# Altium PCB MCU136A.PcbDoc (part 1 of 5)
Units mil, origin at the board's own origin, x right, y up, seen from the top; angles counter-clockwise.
Board outline 3937.01 x 4724.41 mil, 4 copper layers (Top Layer, Signal Layer 1, Signal Layer 2, Bottom Layer), stack 60 mil thick; 390 components, 224 nets, 1130 pads, 1344 vias.
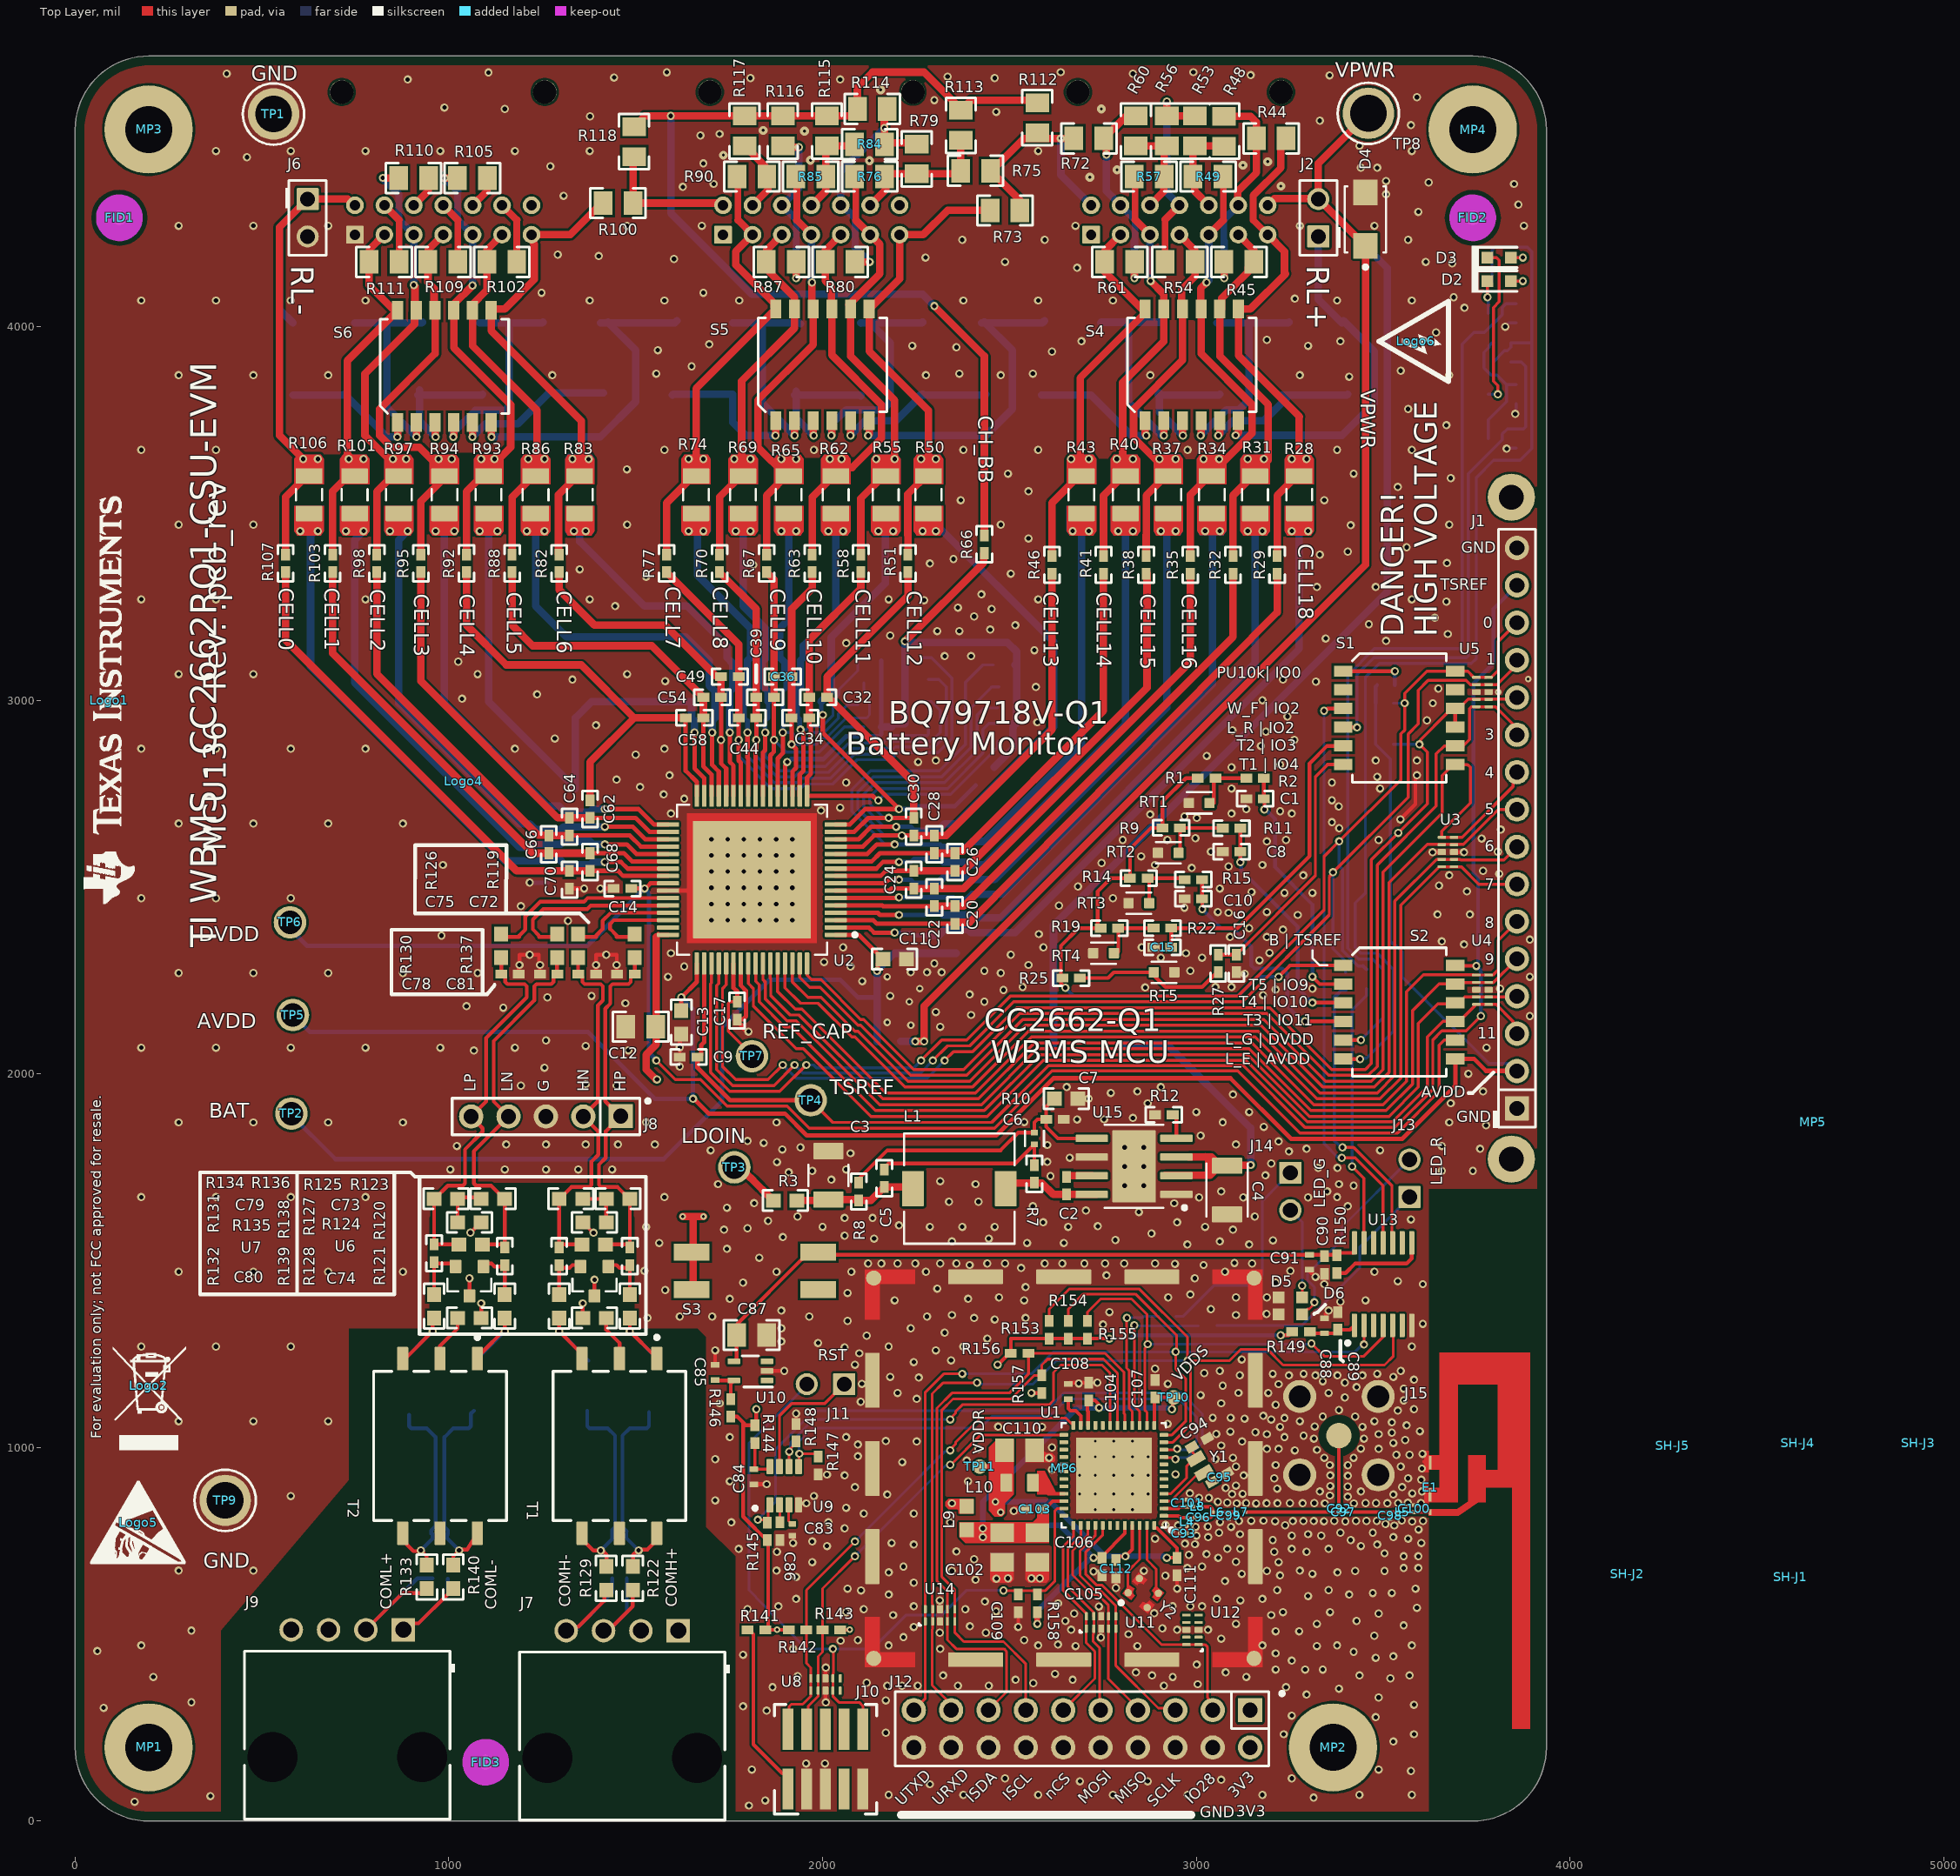
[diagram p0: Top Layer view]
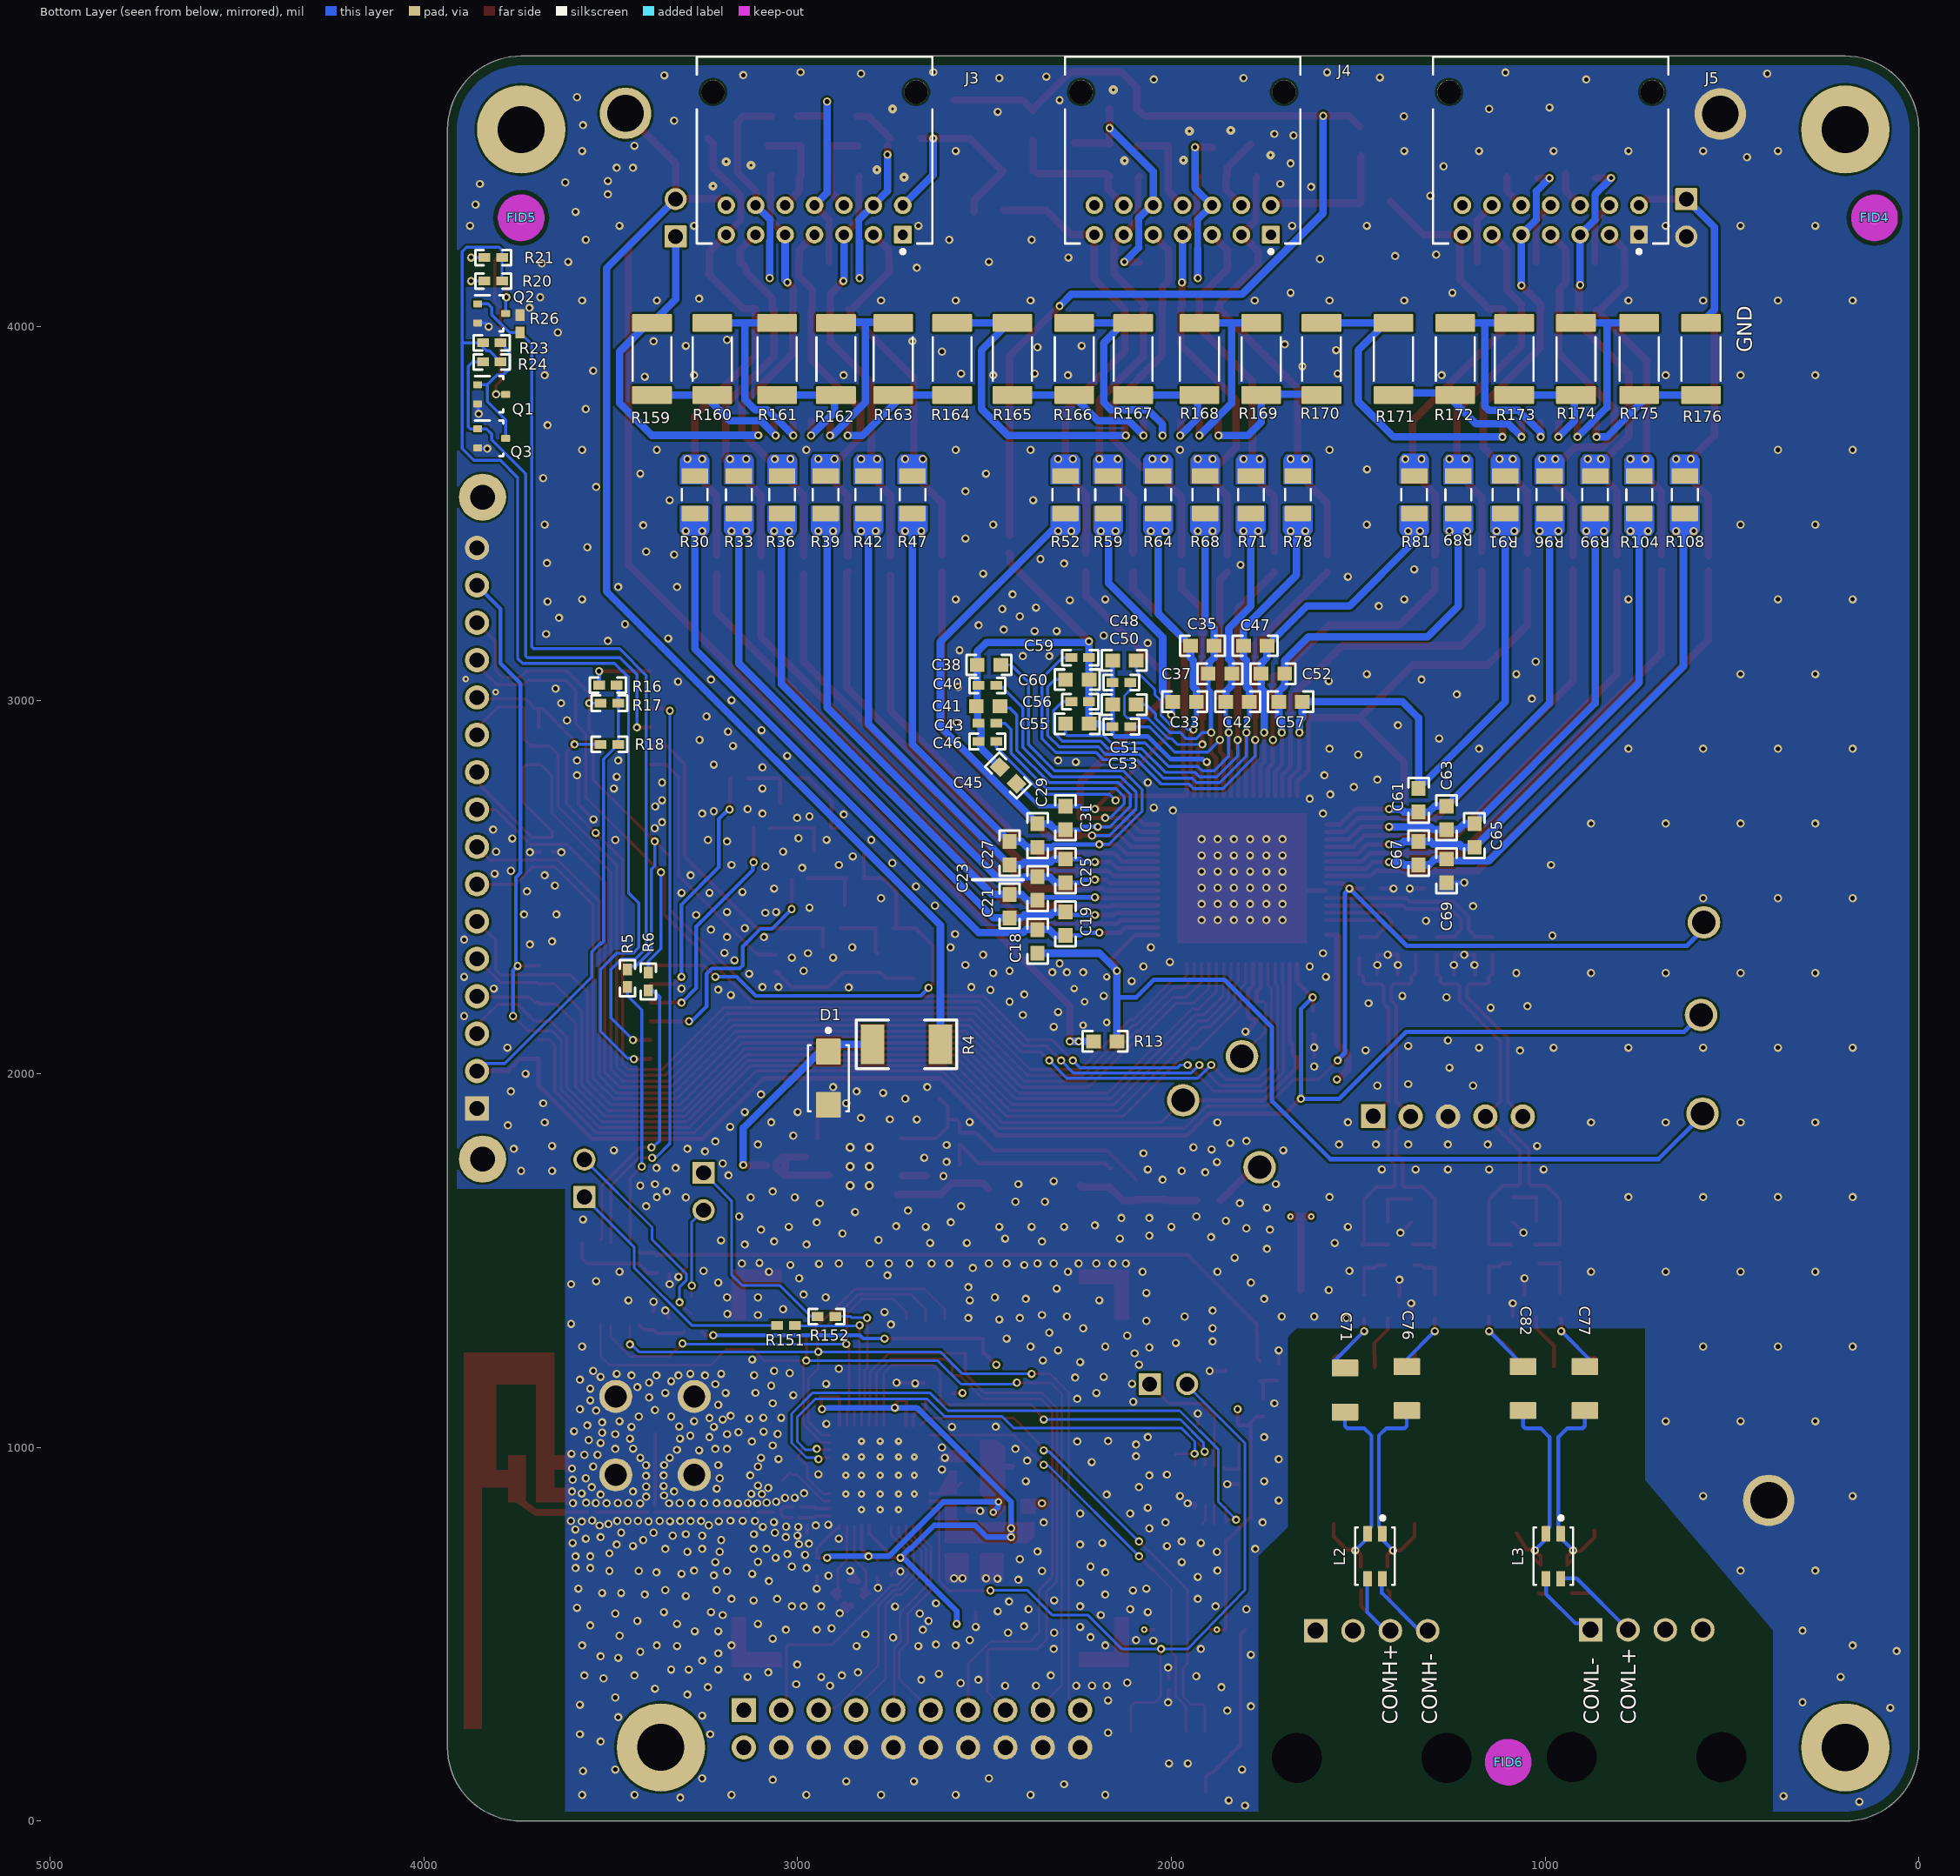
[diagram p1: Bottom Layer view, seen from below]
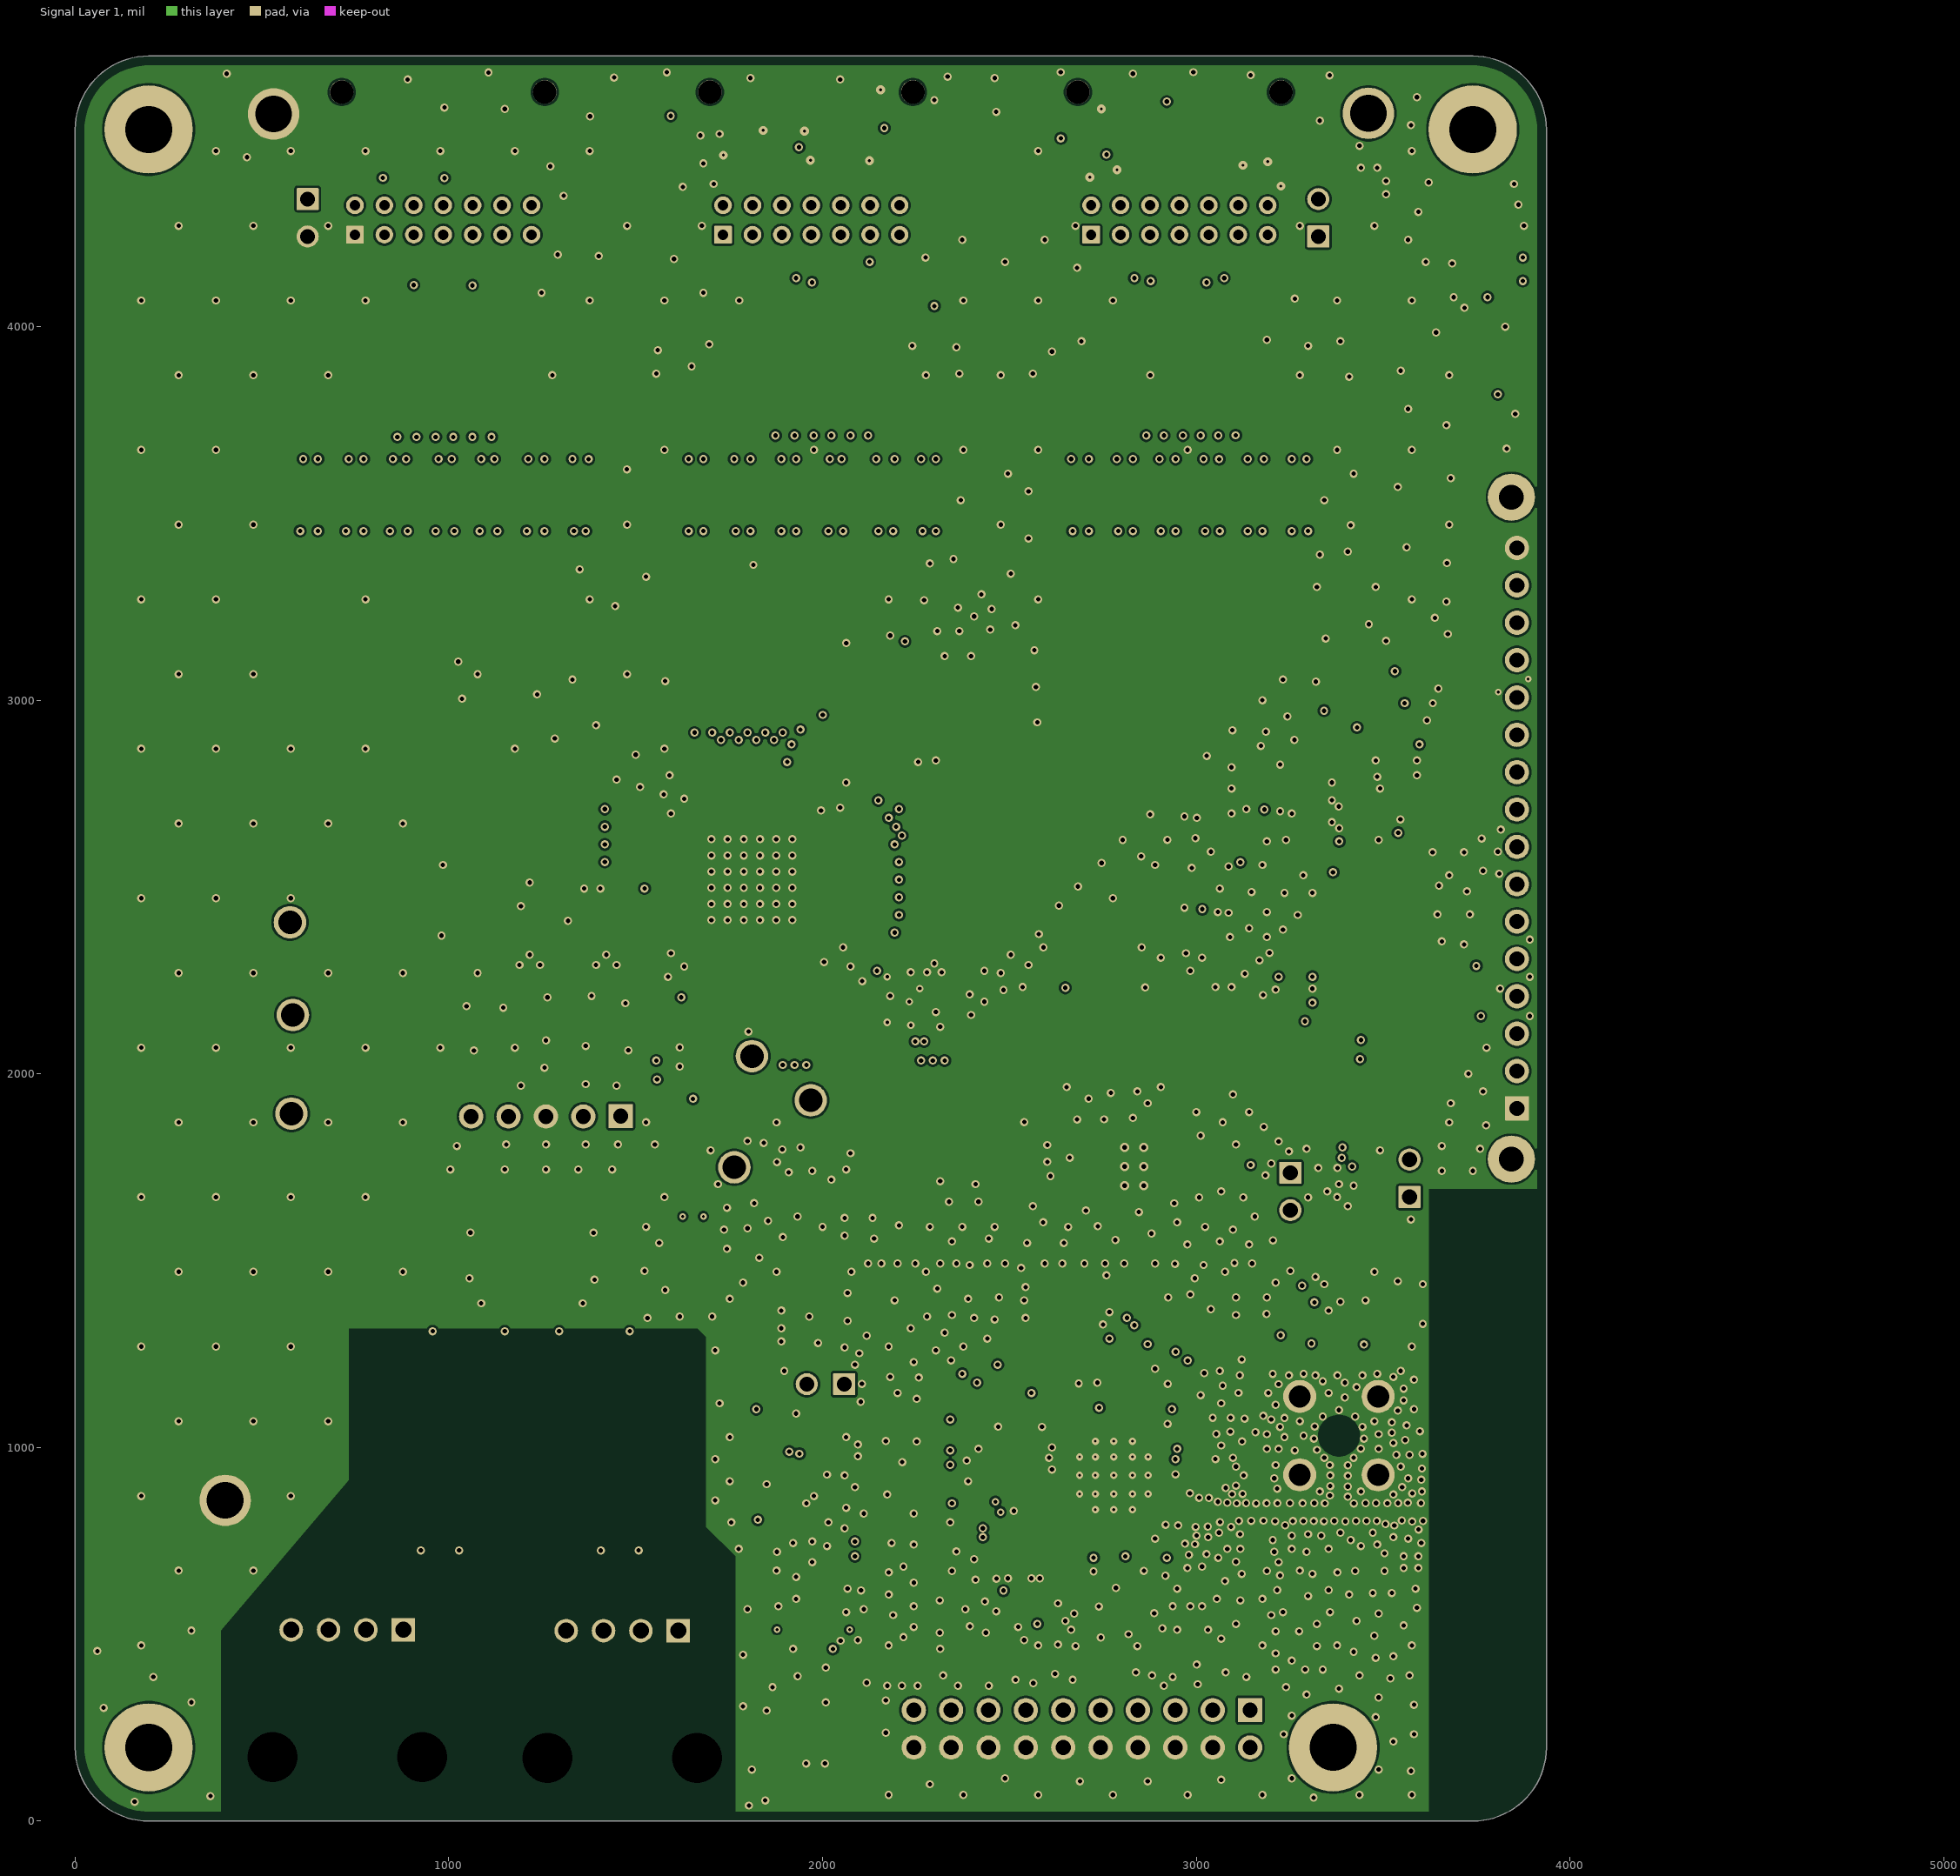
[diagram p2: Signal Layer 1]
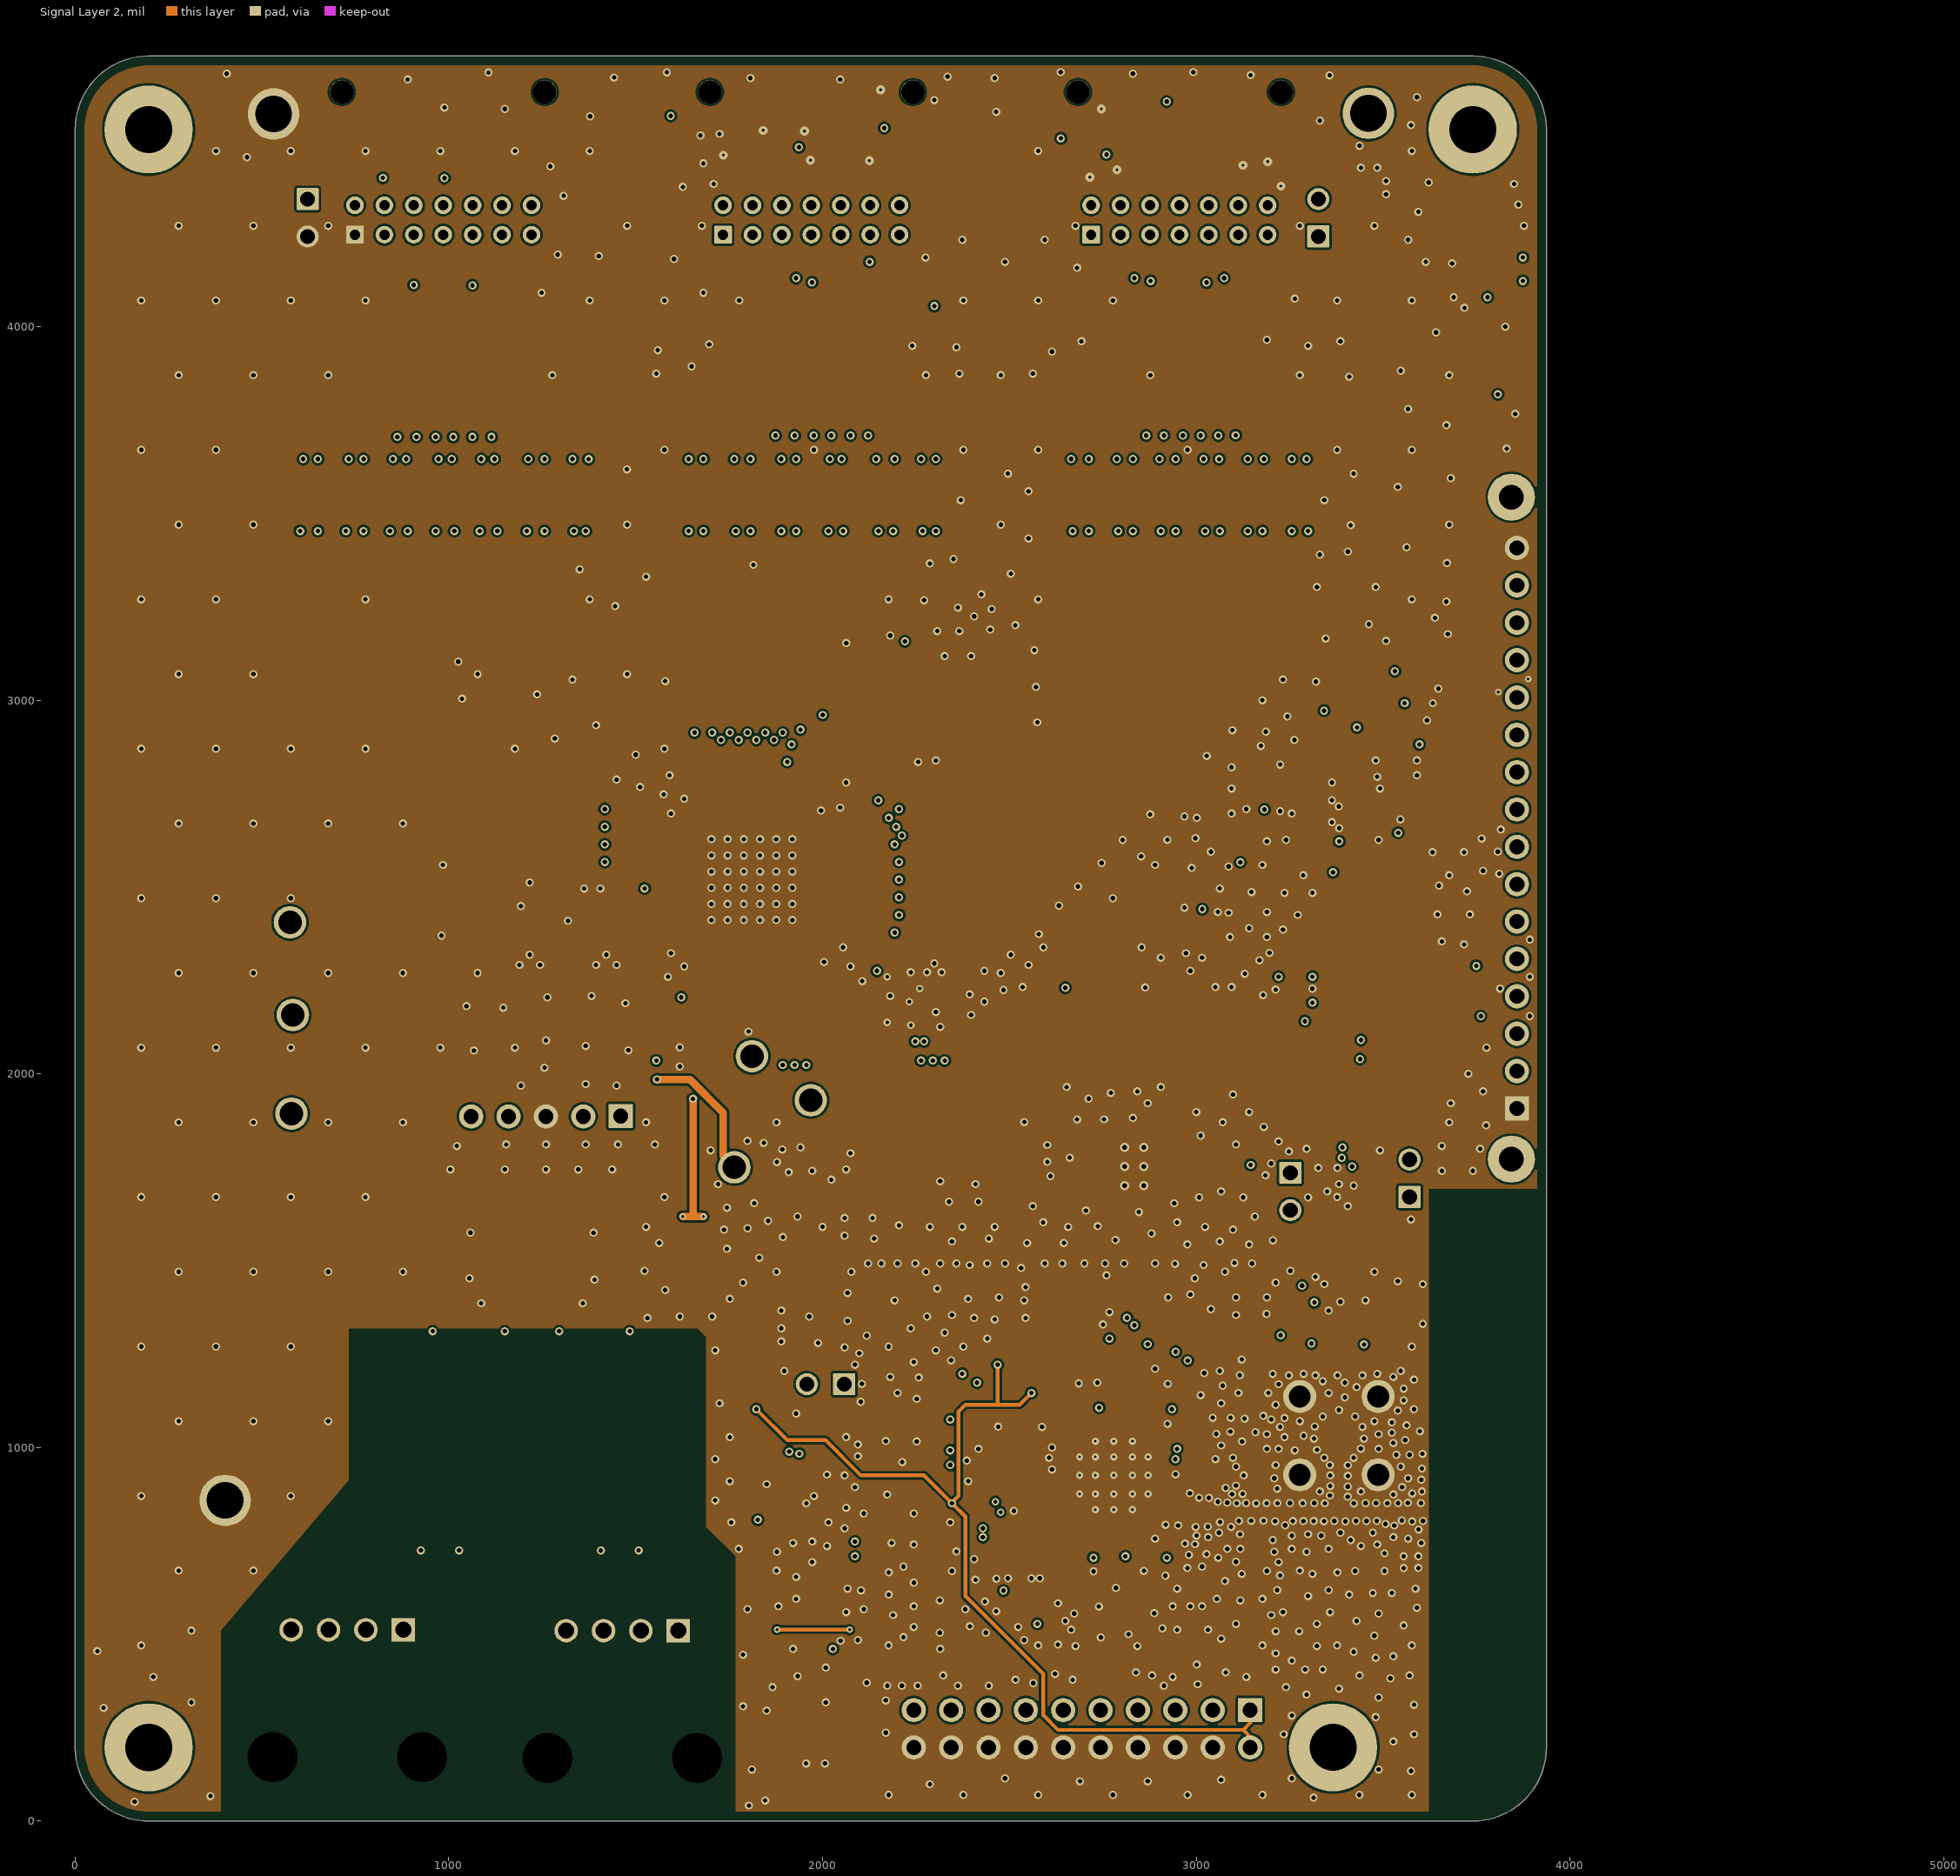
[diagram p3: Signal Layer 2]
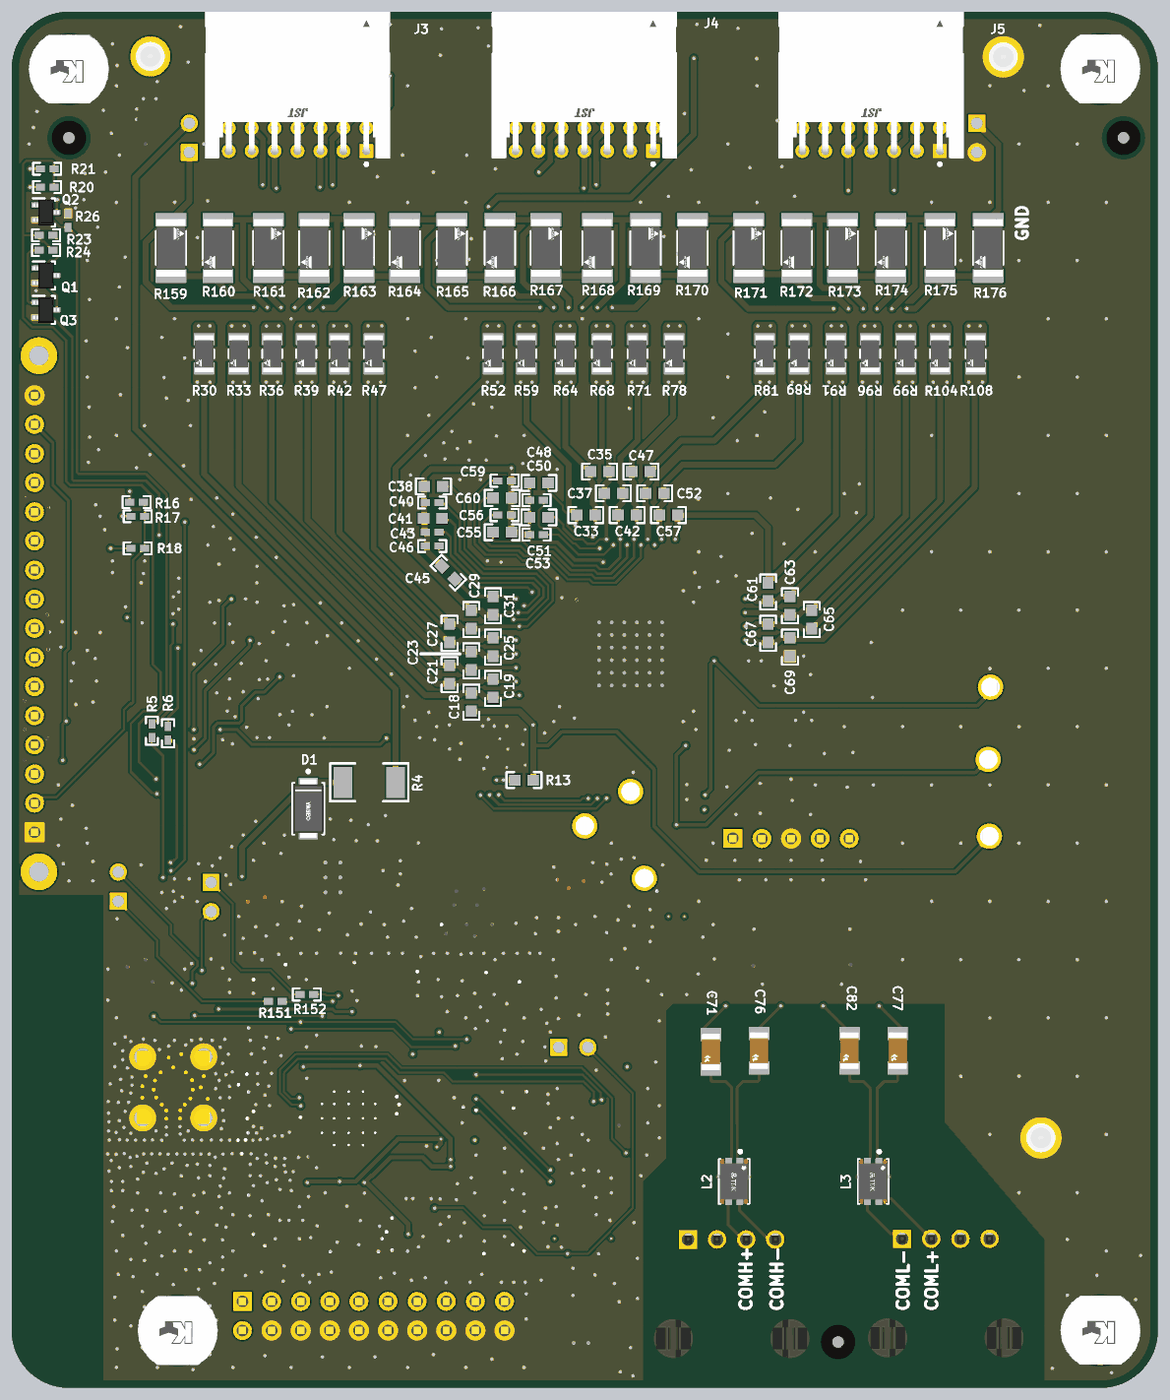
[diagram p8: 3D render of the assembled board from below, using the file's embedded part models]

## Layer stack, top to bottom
Top Solder: solder mask 1, Solder Resist, Dk 3.4
Top Layer: signal copper 3
Dielectric 1: prepreg 8.1, FR-4 High Tg, Dk 4.6
Signal Layer 1: signal copper 1.5
Dielectric 2: core 34.8, FR-4 High Tg, Dk 4.6
Signal Layer 2: signal copper 1.5
Dielectric 3: prepreg 8.1, FR-4 High Tg, Dk 4.6
Bottom Layer: signal copper 3
Bottom Solder: solder mask 1, Solder Resist, Dk 3.4

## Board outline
196.85,0 cw(c196.85,196.85) 0,196.85 0,4527.56 cw(c196.85,4527.56) 196.85,4724.41 3740.16,4724.41 cw(c3740.16,4527.56) 3937.01,4527.56 3937.01,196.85 cw(c3740.16,196.85) 3740.16,0

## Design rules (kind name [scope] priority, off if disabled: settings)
AcuteAngle [All] p1: minimum=4.30000000000000E+0001 checktracksonly=FALSE
AssemblyTestPointUsage [All] p1: valid=2
BoardOutlineClearance BoardOutlineClearance_MountingHoles [OnCopper and InComponentClass('Mounting Holes')] p1: gap=39.37 ignorepadtopadclearanceinfootprint=FALSE
BoardOutlineClearance BoardOutlineClearance_Poly [OnCopper and IsPoly] p2: gap=25 ignorepadtopadclearanceinfootprint=FALSE
BoardOutlineClearance [OnCopper and Not InComponentClass('Logo') and not InComponentClass('FiducialMark') and not InRegion(1000,500,4000,800) and not InPoly] p3: gap=30 ignorepadtopadclearanceinfootprint=FALSE
Clearance Clearance_RF_GND [InNetClass('RF') vs InNet('GND')] p1: gap=6.8 ignorepadtopadclearanceinfootprint=TRUE
Clearance Clearance_Fid [InComponent('FID1') or InComponent('FID2') or InComponent('FID3') or InComponent('FID4') or InComponent('FID5') or InComponent('FID6')] p2: gap=11.81 ignorepadtopadclearanceinfootprint=TRUE
Clearance Clearance_J2 [InComponent('J2')] p3: gap=6 ignorepadtopadclearanceinfootprint=TRUE
Clearance Clearance_Inner1 [OnLayer('Top Inner')] p4: gap=6 ignorepadtopadclearanceinfootprint=TRUE except(15: Arc-Fill Arc-Poly Arc-Region Track-Fill Track-Poly Track-Region SMDPad-Fill SMDPad-Poly SMDPad-Region THPad-Fill THPad-Poly THPad-Region Via-Fill Via-Poly Via-Region Fill-Fill Fill-Poly Fill-Region Poly-Poly Poly-Region Region-Region)
Clearance Clearance_Inner2 [OnLayer('Bottom Inner')] p5: gap=6 ignorepadtopadclearanceinfootprint=TRUE except(15: Arc-Fill Arc-Poly Arc-Region Track-Fill Track-Poly Track-Region SMDPad-Fill SMDPad-Poly SMDPad-Region THPad-Fill THPad-Poly THPad-Region Via-Fill Via-Poly Via-Region Fill-Fill Fill-Poly Fill-Region Poly-Poly Poly-Region Region-Region)
Clearance [All] p6: gap=6 ignorepadtopadclearanceinfootprint=TRUE
ComponentClearance ComponentClearance_Header [InComponent('J17') or InComponent('J19') or InComponent('J23') or InComponent('J8')] p1: gap=0.39 collisioncheckmode=3 verticalgap=10 showdistances=FALSE
ComponentClearance ComponentClearance_MountingHoles_FiducialMarks [InComponentClass('Mounting Holes') vs InComponentClass('FiducialMark')] p2: gap=50 collisioncheckmode=3 verticalgap=10 showdistances=FALSE
ComponentClearance ComponentClearance_Shunt [InComponentClass('Header') vs InComponentClass('Shunt')] p3: gap=0 collisioncheckmode=3 verticalgap=0 showdistances=FALSE
ComponentClearance ComponentClearance_Logo [InComponentClass('Logo')] p4: gap=50 collisioncheckmode=3 verticalgap=10 showdistances=FALSE
ComponentClearance ComponentClearance_ScrewToNut [(HasFootprint('NY PMS 440 0025 PH')) vs (HasFootprint('Keystone_1902C'))] p5: gap=5 collisioncheckmode=3 verticalgap=10 showdistances=FALSE
ComponentClearance ComponentClearance_MountingHoles [InComponentClass('Mounting Holes')] p6: gap=250 collisioncheckmode=3 verticalgap=100000 showdistances=FALSE
ComponentClearance ComponentClearance_SmallPassives [HasFootprint('0201*') or HasFootprint('0402*') or HasFootprint('0508') or HasFootprint('0603*') or HasFootprint('0612') or HasFootprint('0805*') or HasFootprint('0815*') or HasFootprint('0830*') or HasFootprint('1206*') or HasFootprint('1210*') or HasFootprint('1808*') or HasFootprint('1812*') or HasFootprint('1825*') or HasFootprint('2010*') or HasFootprint('2220*') or HasFootprint('2225*') or HasFootprint('2512*') or HasFootprint('2728*') or HasFootprint('3518*') vs HasFootprint('0201*') or HasFootprint('0402*') or HasFootprint('0508') or HasFootprint('0603*') or HasFootprint('0612') or HasFootprint('0805*') or HasFootprint('0815*') or HasFootprint('0830*') or HasFootprint('1206*') or HasFootprint('1210*') or HasFootprint('1808*') or HasFootprint('1812*') or HasFootprint('1825*') or HasFootprint('2010*') or HasFootprint('2220*') or HasFootprint('2225*') or HasFootprint('2512*') or HasFootprint('2728*') or HasFootprint('3518*')] p7: gap=10 collisioncheckmode=3 verticalgap=10 showdistances=FALSE
ComponentClearance ComponentClearance_THtoSMT [IsThruComponent vs IsSMTComponent] p8: gap=19.68 collisioncheckmode=3 verticalgap=30 showdistances=FALSE
ComponentClearance ComponentClearance_THtoTH [IsThruComponent vs IsThruComponent] p9: gap=30 collisioncheckmode=3 verticalgap=30 showdistances=FALSE
ComponentClearance [All] p10: gap=10 collisioncheckmode=3 verticalgap=10 showdistances=FALSE
DiffPairsRouting [All] p1: maxlimit=100 minlimit=10 mostfreqgap=10 toplayer_minwidth=7.87 toplayer_maxwidth=15 toplayer_prefwidth=10 midlayer2_minwidth=7.87 midlayer2_maxwidth=15 midlayer2_prefwidth=10 midlayer3_minwidth=7.87 midlayer3_maxwidth=15 midlayer3_prefwidth=10 bottomlayer_minwidth=7.87 bottomlayer_maxwidth=15 bottomlayer_prefwidth=10 maxuncoupledlength=1000
FabricationTestPointUsage TestPointUsage [All] p1: valid=2 allowmultiple=FALSE
FabricationTestpoint Testpoint [All] p1: side=3 testpointundercomponent=TRUE minsize=40 maxsize=100 preferedsize=60 minholesize=0 maxholesize=40 preferedholesize=32 testpointgrid=1 allowsidetop=TRUE allowsidebottom=TRUE usegrid=TRUE gridtolerance=0.01
FanoutControl Fanout_LCC [IsLCC] p1: bgadir=Out bgaviamode=Centered fanoutstyle=Auto fanoutdirection=Alternating viagrid=1 // Fanout_LCC (Default Rule)
FanoutControl Fanout_BGA [IsBGA] p2: bgadir=Out bgaviamode=Centered fanoutstyle=Auto fanoutdirection=Alternating viagrid=1 // Fanout_BGA (Default Rule)
FanoutControl Fanout_Default [All] p4: bgadir=Out bgaviamode=Centered fanoutstyle=Auto fanoutdirection=Alternating viagrid=1 // Fanout_Default (Default Rule)
FanoutControl Fanout_Small [(CompPinCount < 5)] p5: bgadir=Out bgaviamode=Centered fanoutstyle=Auto fanoutdirection=OutThenIn viagrid=1 // Fanout_Small (Default Rule)
HoleSize [All] p1: absolutevalues=TRUE maxlimit=251 minlimit=7.87 maxpercent=80.000 minpercent=20.000
MinimumAnnularRing MinimumAnnularRing_ThermalPadVias [IsVia and InAnyComponent] p1: minimumring=5.9
MinimumAnnularRing [All] p2: minimumring=3.94
MinimumSolderMaskSliver MinimumSolderMaskSliver_Logo [InComponentClass('Logo') vs InComponentClass('Logo')] p1: minsoldermaskwidth=0.7
MinimumSolderMaskSliver [All] p2: minsoldermaskwidth=3.94
PlaneClearance [All] p1: clearance=3.94
PlaneConnect [All] p1: planeconnectstyle=Direct reliefexpansion=10 reliefentries=4 reliefconductorwidth=10 reliefairgap=10
PolygonConnect [All] p1: connectstyle=Direct reliefconductorwidth=10 reliefentries=4 polygonreliefangle="90 Angle" airgapwidth=10
RoutingVias ThermalPadVias [IsVia and InAnyComponent] p1: holewidth=7.87 width=19.68 viastyle="Through Hole" minholewidth=7.87 minwidth=11.81 maxholewidth=19.68 maxwidth=27.56
RoutingVias [All] p2: holewidth=16 width=34 viastyle="Through Hole" minholewidth=7.87 minwidth=15 maxholewidth=40 maxwidth=65
SilkToBoardRegionClearance [Not ((IsComment or IsDesignator) And (Hide <> 'False')) and not InRegion(1000,500,4000,800)] p1:
SilkToSilkClearance SilkToSilkClearance_Pb-FreeLogo [(HasFootprint('Pb-Free_Overlay_Medium') OR HasFootprint('Pb-Free_Overlay_Small')) vs (HasFootprint('Pb-Free_Overlay_Medium') OR HasFootprint('Pb-Free_Overlay_Small'))] p1: silktosilkclearance=0
SilkToSilkClearance [All] p2: silktosilkclearance=3.94
SilkToSolderMaskClearance SilkToComponentPadClearance [(IsPad or IsFill or IsRegion) and InAnycomponent] p1: minsilkscreentomaskgap=5 clearancetoexposedcopper=TRUE
SilkToSolderMaskClearance "Silk to Solder Mask Opening" [All] p2: minsilkscreentomaskgap=3.94 clearancetoexposedcopper=FALSE
SolderMaskExpansion [All] p1: expansion=1.97 istentingtop=FALSE
SupplyNets "Schematic Supply Nets_7" [InNet('VCCA')] p1: voltage=0.000
SupplyNets "Schematic Supply Nets_6" [InNet('GND')] p2: voltage=0.000
SupplyNets "Schematic Supply Nets_5" [InNet('VDDR')] p3: voltage=0.000
SupplyNets "Schematic Supply Nets_4" [InNet('CELL18_Lad')] p4: voltage=0.000
SupplyNets "Schematic Supply Nets_3" [InNet('3V3_CC')] p5: voltage=0.000
SupplyNets "Schematic Supply Nets_2" [InNet('VDDS')] p6: voltage=0.000
SupplyNets "Schematic Supply Nets_1" [InNet('WL_PWR')] p7: voltage=0.000
SupplyNets "Schematic Supply Nets" [InNet('AVDD')] p8: voltage=0.000
UnRoutedNet [All] p1: checkbadconnections=TRUE
Width RF [InNetClass('RF')] p1: maxlimit=9.4 minlimit=4.78 preferedwidth=9.4 toplayer_minwidth=9.4 toplayer_maxwidth=9.4 midlayer2_maxwidth=5.9 midlayer2_prefwidth=4.78 midlayer3_maxwidth=5.9 midlayer3_prefwidth=4.78 bottomlayer_minwidth=9.4 impedanceprofiledriven=TRUE impedanceprofileid={D86C3CD7-6854-4D75-BA5A-4B6A5C1DC38E} impedanceprofilevalue=50.000000 minimp=50.000000 maximp=50.000000 favimp=50.000000 checkconnectedcopper=TRUE
Width Width_1 [All] p2: maxlimit=40 minlimit=7 preferedwidth=10 minimp=50.000000 maximp=50.000000 favimp=50.000000
13 further rules are at their usual default settings.

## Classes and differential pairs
component class AssemblyNote: ZZ1 ZZ2 ZZ3 ZZ4
component class Shunt: SH-J1 SH-J2 SH-J3 SH-J4 SH-J5
component class MCU136A_Resistive_Ladder: R159 R160 R161 R162 R163 R164 R165 R166 R167 R168 R169 R170 R171 R172 R173 R174 R175 R176 S4 S5 S6
net class RF: NetC92_1 NetC92_2 NetC93_2 NetC96_2 NetC97_2 NetC99_2 NetC100_2 RF1_N RF1_P
component class MCU136A_RF: C83 C84 C85 C86 C87 C88 C89 C90 C91 C92 C93 C94 C95 C96 C97 C98 C99 C100 C101 C102 C103 C104 C105 C106 C107 C108 C109 C110 C111 C112 D5 D6 E1 J10 J11 J12 J13 J14 J15 L4 L5 L6 L7 L8 L9 L10 R141 R142 R143 R144 R145 R146 R147 R148 R149 R150 R151 R152 R153 R154 R155 R156 R157 R158 SH-J3 SH-J4 SH-J5 TP9 TP10 TP11 U1 U8 U9 U10 U11 U12 U13 U14 Y1 Y2
component class MCU136A_Hardware: !PCB1 FID1 FID2 FID3 FID4 FID5 FID6 Logo1 Logo2 Logo4 Logo5 Logo6 MP1 MP2 MP3 MP4 MP5 MP6 ZZ1 ZZ2 ZZ3 ZZ4
component class MCU136A_Connector: C18 C19 C20 C21 C22 C23 C24 C25 C26 C27 C28 C29 C30 C31 C32 C33 C34 C35 C36 C37 C38 C39 C40 C41 C42 C43 C44 C45 C46 C47 C48 C49 C50 C51 C52 C53 C54 C55 C56 C57 C58 C59 C60 C61 C62 C63 C64 C65 C66 C67 C68 C69 C70 D4 J2 J3 J4 J5 J6 R28 R29 R30 R31 R32 R33 R34 R35 R36 R37 R38 R39 R40 R41 R42 R43 R44 R45 R46 R47 R48 R49 R50 R51 R52 R53 R54 R55 R56 R57 R58 R59 R60 R61 R62 R63 R64 R65 R66 R67 R68 R69 R70 R71 R72 R73 R74 R75 R76 R77 R78 R79 R80 R81 R82 R83 R84 R85 R86 R87 R88 R89 R90 R91 R92 R93 R94 R95 R96 R97 R98 R99 R100 R101 R102 R103 R104 R105 R106 R107 R108 R109 R110 R111 R112 R113 R114 R115 R116 R117 R118 SH-J1 SH-J2 TP8
component class MCU136A_BQ7971x: C1 C2 C3 C4 C5 C6 C7 C8 C9 C10 C11 C12 C13 C14 C15 C16 C17 D1 D2 D3 J1 L1 Q1 Q2 Q3 R1 R2 R3 R4 R5 R6 R7 R8 R9 R10 R11 R12 R13 R14 R15 R16 R17 R18 R19 R20 R21 R22 R23 R24 R25 R26 R27 RT1 RT2 RT3 RT4 RT5 S1 S2 S3 TP1 TP2 TP3 TP4 TP5 TP6 TP7 U2 U3 U4 U5 U15
component class Logo: Logo1
component class FiducialMark: FID1 FID2 FID3 FID4 FID5 FID6
component class MCU136A_Communication: C71 C72 C73 C74 C75 C76 C77 C78 C79 C80 C81 C82 J7 J8 J9 L2 L3 R119 R120 R121 R122 R123 R124 R125 R126 R127 R128 R129 R130 R131 R132 R133 R134 R135 R136 R137 R138 R139 R140 T1 T2 U6 U7
component class Header: J1 J2 J6 J8 J11 J12 J13 J14
differential pair COMLR: +COMLR_P -COMLR_N
differential pair COMHR: +COMHR_P -COMHR_N
differential pair COMLC: +COMLC_P -COMLC_N
differential pair COMHC: +COMHC_P -COMHC_N
differential pair COML_R2: +COML_R2_P -COML_R2_N
differential pair COML_R1: +COML_R1_P -COML_R1_N
differential pair COMH_R2: +COMH_R2_P -COMH_R2_N
differential pair COMH_R1: +COMH_R1_P -COMH_R1_N
differential pair COML_ISO: +COML_ISO_P -COML_ISO_N
differential pair COMH_ISO: +COMH_ISO_P -COMH_ISO_N
differential pair COML: +COML_P -COML_N
differential pair COMH: +COMH_P -COMH_N

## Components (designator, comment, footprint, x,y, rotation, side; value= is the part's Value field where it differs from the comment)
C1 "GCM155R71H104KE02D" 0402 3157.48,2736.22 r180 top value=0.1uF
C2 "GCM155R71H222KA37D" 0402 2653.16,1700.79 r270 top value=2200pF
C3 "GCM32EC71A476KE02K" FP-GCM32EC71A476KE02K_1210-MFG 2015.75,1728.35 r270 top value=47µF
C4 "GCJ32DC72A475KE01L" FP-GCJ32DC72A475KE01L_1210-MFG 3082.68,1688.98 r90 top value=4.7µF
C5 "GCM155R71H332KA37D" 0402 2165.35,1720.47 r90 top value=3300pF
C6 "GCM1555C1H560FA16D" FP-GCM1555C1H560FA16D_0402-MFG 2566.93,1826.77 r270 top value=56pF
C7 "GCM188R72A103KA37J" 0603 2652.07,1933.43 r0 top value=0.01uF
C8 "GCM155R71H104KE02D" 0402 3094.49,2594.49 r180 top value=0.1uF
C9 "GCM155C71A474KE36D" 0402 1641.73,2044.79 r180 top value=0.47uF
C10 "GCM155R71H104KE02D" 0402 2992.13,2468.5 r180 top value=0.1uF
C11 "GCM188R72A103KA37J" 0603 2192.91,2307.09 r0 top value=0.01uF
C12 "GCJ21BL81E105KA01L" 0805_HV 1513.44,2125.98 r180 top value=1uF
C13 "GCM188R71C105KA64D" 0603 1622.05,2137.8 r270 top value=1uF
C14 "GCM155C71A474KE36D" 0402 1464.57,2496.06 r180 top value=0.47uF
C15 "GCM155R71H104KE02D" 0402 2909.45,2338.58 r180 top value=0.1uF
C16 "GCM155R71H104KE02D" 0402 3107.46,2295.28 r270 top value=0.1uF
C17 "GCM155C71A474KE36D" 0402 1771.65,2169.29 r270 top value=0.47uF
C18 "GCM188R71H104KA57D" 0603 2358.27,2354.33 r90 bottom value=0.1uF
C19 "GCM188R71H104KA57D" 0603 2283.46,2401.57 r90 bottom value=0.1uF
C20 "GCM155R71H472KA37D" 0402 2354.33,2425.2 r90 top value=4700pF
C21 "GCM188R71H104KA57D" 0603 2433.07,2448.82 r90 bottom value=0.1uF
C22 "GCM155R71H472KA37D" 0402 2299.21,2472.44 r90 top value=4700pF
C23 "GCM188R71H104KA57D" 0603 2358.27,2496.06 r90 bottom value=0.1uF
C24 "GCM155R71H472KA37D" 0402 2244.09,2519.68 r90 top value=4700pF
C25 "GCM188R71H104KA57D" 0603 2283.46,2543.31 r90 bottom value=0.1uF
C26 "GCM155R71H472KA37D" 0402 2354.33,2566.93 r90 top value=4700pF
C27 "GCM188R71H104KA57D" 0603 2433.07,2590.55 r90 bottom value=0.1uF
C28 "GCM155R71H472KA37D" 0402 2299.21,2614.17 r90 top value=4700pF
C29 "GCM188R71H104KA57D" 0603 2358.27,2637.8 r90 bottom value=0.1uF
C30 "GCM155R71H472KA37D" 0402 2244.09,2661.42 r90 top value=4700pF
C31 "GCM188R71H104KA57D" 0603 2283.46,2685.04 r90 bottom value=0.1uF
C32 "GCM155R71H472KA37D" 0402 1988.19,3007.87 r180 top value=4700pF
C33 "GCM188R71H104KA57D" 0603 1964.57,2996.06 r180 bottom value=0.1uF
C34 "GCM155R71H472KA37D" 0402 1940.94,2952.76 r180 top value=4700pF
C35 "GCM188R71H104KA57D" 0603 1917.32,3145.67 r180 bottom value=0.1uF
C36 "GCM155R71H472KA37D" 0402 1893.7,3062.99 r180 top value=4700pF
C37 "GCM188R71H104KA57D" 0603 1870.08,3070.87 r180 bottom value=0.1uF
C38 "GCM188R71H104KA57D" 0603 2488.19,3094.53 r180 bottom value=0.1uF
C39 "GCM155R71H472KA37D" 0402 1846.46,3007.87 r180 top value=4700pF
C40 "GCM155R71H472KA37D" 0402 2492.13,3039.42 r0 bottom value=4700pF
C41 "GCM188R71H104KA57D" 0603 2490.51,2984.25 r180 bottom value=0.1uF
C42 "GCM188R71H104KA57D" 0603 1822.83,2996.06 r180 bottom value=0.1uF
C43 "GCM155R71H472KA37D" 0402 2492.13,2938.17 r0 bottom value=4700pF
C44 "GCM155R71H472KA37D" 0402 1799.21,2952.76 r180 top value=4700pF
C45 "GCM188R71H104KA57D" 0603 2437.01,2798.72 r225 bottom value=0.1uF
C46 "GCM155R71H472KA37D" 0402 2492.13,2889.76 r0 bottom value=4700pF
C47 "GCM188R71H104KA57D" 0603 1775.59,3145.67 r180 bottom value=0.1uF
C48 "GCM188R71H104KA57D" 0603 2125.98,3106.3 r180 bottom value=0.1uF
C49 "GCM155R71H472KA37D" 0402 1751.97,3062.99 r180 top value=4700pF
C50 "GCM155R71H472KA37D" 0402 2133.86,3047.24 r0 bottom value=4700pF
C51 "GCM188R71H104KA57D" 0603 2125.98,2988.19 r180 bottom value=0.1uF
C52 "GCM188R71H104KA57D" 0603 1728.35,3070.87 r180 bottom value=0.1uF
C53 "GCM155R71H472KA37D" 0402 2133.86,2929.13 r0 bottom value=4700pF
C54 "GCM155R71H472KA37D" 0402 1704.72,3007.87 r180 top value=4700pF
C55 "GCM188R71H104KA57D" 0603 2251.97,2937.01 r0 bottom value=0.1uF
C56 "GCM155R71H472KA37D" 0402 2244.09,2996.06 r180 bottom value=4700pF
C57 "GCM188R71H104KA57D" 0603 1681.1,2996.06 r180 bottom value=0.1uF
C58 "GCM155R71H472KA37D" 0402 1657.48,2952.76 r180 top value=4700pF
C59 "GCM155R71H472KA37D" 0402 2244.09,3114.17 r180 bottom value=4700pF
C60 "GCM188R71H104KA57D" 0603 2251.97,3055.12 r0 bottom value=0.1uF
C61 "GCM188R71H104KA57D" 0603 1338.58,2732.28 r270 bottom value=0.1uF
C62 "GCM155R71H472KA37D" 0402 1377.95,2708.66 r270 top value=4700pF
C63 "GCM188R71H104KA57D" 0603 1263.78,2685.04 r270 bottom value=0.1uF
C64 "GCM155R71H472KA37D" 0402 1322.83,2661.42 r270 top value=4700pF
C65 "GCM188R71H104KA57D" 0603 1188.98,2637.8 r270 bottom value=0.1uF
C66 "GCM155R71H472KA37D" 0402 1267.72,2614.17 r270 top value=4700pF
C67 "GCM188R71H104KA57D" 0603 1338.58,2590.55 r270 bottom value=0.1uF
C68 "GCM155R71H472KA37D" 0402 1377.95,2566.93 r270 top value=4700pF
C69 "GCM188R71H104KA57D" 0603 1263.78,2543.31 r270 bottom value=0.1uF
C70 "GCM155R71H472KA37D" 0402 1322.83,2519.68 r270 top value=4700pF
C71 "1206Y2K00222KET" FP-1206Y2K00222KET_1206-MFG 1535.43,1153.54 r270 bottom value=2.2nF
C72 "CGA2B2X7R1H221K050BA" 0402 1473.9,2266.62 r180 top value=220pF
C73 "GCM188R71H103KA37D" 0603 1389.76,1602.36 r0 top value=0.01uF
C74 "GCM1885C1H101JA16J" 0603 1389.76,1346.46 r0 top value=100pF
C75 "CGA2B2X7R1H221K050BA" 0402 1370.5,2266.62 r180 top value=220pF
C76 "1206Y2K00222KET" FP-1206Y2K00222KET_1206-MFG 1370.08,1157.48 r270 bottom value=2.2nF
C77 "1206Y2K00222KET" FP-1206Y2K00222KET_1206-MFG 893.7,1157.48 r270 bottom value=2.2nF
C78 "CGA2B2X7R1H221K050BA" 0402 1163.69,2266.62 r0 top value=220pF
C79 "GCM188R71H103KA37D" 0603 1055.12,1602.36 r180 top value=0.01uF
C80 "GCM1885C1H101JA16J" 0603 1055.12,1346.46 r180 top value=100pF
C81 "CGA2B2X7R1H221K050BA" 0402 1267.1,2266.62 r0 top value=220pF
C82 "1206Y2K00222KET" FP-1206Y2K00222KET_1206-MFG 1059.06,1157.48 r270 bottom value=2.2nF
C83 "GCM155R71E473KA55D" FP-GCM155R71E473KA55D_0402-MFG 1919.32,779.53 r270 top value=47nF
C84 "GCM155C71A105KE38D" 0402_070 1816.11,921.26 r270 top value=1uF
C85 "GCM155C71A105KE38D" 0402_070 1712.6,1200.79 r90 top value=1uF
C86 "GCM155R71E103KA37D" 0402 1885.83,775.59 r270 top value=0.01uF
C87 "GCM21BR71E225KA73L" 0805_HV 1810.32,1300.96 r180 top value=2.2uF
C88 "GCM155C71A105KE38D" 0402_070 3343.05,1325.45 r90 top value=1uF
C89 "GCM155R71A104KA55D" 0402 3378.83,1338.58 r90 top value=0.1uF
C90 "GCM155R71A104KA55D" 0402 3342.92,1488.19 r270 top value=0.1uF
C91 "GCM155C71A105KE38D" 0402_070 3303.15,1496.06 r270 top value=1uF
C92 "GCQ0335C1H120GB01D" FP-GCQ0335C1H120GB01D_0201-MFG 3381.89,836 r90 top value=12pF
C93 "GCQ0335C1H120GB01D" FP-GCQ0335C1H120GB01D_0201-MFG 2965.5,770 r0 top value=12pF
C94 "GCM1555C1H120JA16J" 0402 3008.68,1012.55 r30 top value=12pF
C95 "GCM1555C1H120JA16J" 0402 3062.49,919.13 r30 top value=12pF
C96 "GCQ0335C1H1R0WB01D" FP-GCQ0335C1H1R0WB01D_0201-MFG 3005.49,812.09 r0 top value=1pF
C97 "GCQ0335C1H120GB01D" FP-GCQ0335C1H120GB01D_0201-MFG 3392.3,826.77 r0 top value=12pF
C98 "GCQ0335C1H1R1BB01D" FP-GCQ0335C1H1R1BB01D_0201-MFG 3519,817.4 r90 top value=1.1pF
C99 "GCQ0335C1H1R0WB01D" FP-GCQ0335C1H1R0WB01D_0201-MFG 3087,817.4 r90 top value=1pF
C100 "GCQ0335C1H1R0WB01D" FP-GCQ0335C1H1R0WB01D_0201-MFG 3582.68,836.1 r270 top value=1pF
C101 "GCQ0335C1H1R0WB01D" FP-GCQ0335C1H1R0WB01D_0201-MFG 2974.87,850.8 r270 top value=1pF
C102 "GCM21BD70J226ME36L" 0805_HV 2480.32,732.28 r270 top value=22uF
C103 "GCM155R71A104KA55D" 0402 2566.93,834.65 r180 top value=0.1uF
C104 "GCM155R71A104KA55D" 0402 2712.6,1149.61 r90 top value=0.1uF
C105 "GCM155R71A104KA55D" 0402 2748.03,681.1 r270 top value=0.1uF
C106 "GCM21BD70J226ME36L" 0805_HV 2574.8,732.28 r270 top value=22uF
C107 "GCM155R71A104KA55D" 0402 2889.73,1157.19 r90 top value=0.1uF
C108 "GCM155C71A105KE38D" 0402_070 2657.48,1149.61 r90 top value=1uF
C109 "GCM155R71A104KA55D" 0402 2523.62,582.68 r270 top value=0.1uF
C110 "GCM21BD70J226ME36L" 0805_HV 2527.56,992.13 r0 top value=22uF
C111 "GCM155R71A104KA55D" 0402 2948.82,681.1 r270 top value=0.1uF
C112 "GCM155R71A104KA55D" 0402 2785.28,675.1 r270 top value=0.1uF
D1 "SMAJ85A-AT/TR13" FP-SMAJ85A-AT/TR13_SMA-MFG 2918.07,1988.19 r270 bottom
D2 "150060VS75000" WL-SMCW_GREEN 3811.02,4122.05 r0 top value=Green
D3 "150060RS75000" WL-SMCW_RED 3811.02,4185.04 r0 top value=Red
D4 "SMAJ85A-AT/TR13" FP-SMAJ85A-AT/TR13_SMA-MFG 3452.76,4287.4 r90 top
D5 "150060VS75000" WL-SMCW_GREEN 3251.97,1401.57 r0 top value=Green
D6 "150060RS75000" WL-SMCW_RED 3251.97,1356.17 r0 top value=Red
E1 "ANTENNA_DN007A" ANTENNA_DN007A 3626,826.5 r90 top net-tie
FID1 "Fiducial" Fiducial10-30 118.11,4291.34 r0 top
FID2 "Fiducial" Fiducial10-30 3740.16,4291.34 r0 top
FID3 "Fiducial" Fiducial10-30 1098.43,157.48 r90 top
FID4 "Fiducial" Fiducial10-30 118.11,4291.34 r90 bottom
FID5 "Fiducial" Fiducial10-30 3740.16,4291.34 r90 bottom
FID6 "Fiducial" Fiducial10-30 1098.43,157.48 r90 bottom
J1 "TSW-116-07-G-S" TSW-116-07-G-S 3858.3,2657.48 r90 top
J2 "PEC02SAAN" CONN_PEC02SAAN 3326.77,4291.34 r90 top
J3 "S14B-PUDSS-1(LF)(SN)" FP-S14B-PUDSS-1(LF)(SN)_CONN_HDR14-MFG 2955,4472.44 r180 bottom
J4 "S14B-PUDSS-1(LF)(SN)" FP-S14B-PUDSS-1(LF)(SN)_CONN_HDR14-MFG 1970,4472.44 r180 bottom
J5 "S14B-PUDSS-1(LF)(SN)" FP-S14B-PUDSS-1(LF)(SN)_CONN_HDR14-MFG 985,4472.44 r180 bottom
J6 "PEC02SAAN" CONN_PEC02SAAN 622.05,4291.34 r270 top
J7 "70551-0038" Molex_70551-0038 1463.93,509.45 r270 top
J8 "TSW-105-07-G-S" TSW-105-07-X-S 1259.84,1885.83 r180 top
J9 "70551-0038" Molex_70551-0038 728.14,511.81 r270 top
J10 "FTSH-105-01-F-DV-K" Samtec_FTSH-105-01-x-DV-K 2007.87,165.48 r90 top
J11 "PEC02SAAN" CONN_PEC02SAAN 2007.87,1169.29 r180 top
J12 "TSW-110-07-G-D" TSW-110-07-G-D 2694.09,246.85 r180 top
J13 "PEC02SAAN" CONN_PEC02SAAN 3570.87,1720.47 r90 top
J14 "PEC02SAAN" CONN_PEC02SAAN 3251.97,1685.04 r270 top
J15 "SMA-J-P-H-ST-MT1" Samtec_SMA-J-P-H-ST-MT1 3381.89,1031.5 r90 top
L1 "SRR0735HA-820M" FP-SRR0735HA-820M-NO_KEEPOUTS-MFG 2366.14,1692.91 r0 top value=82uH
L2 "ACT1210R-101-2P-TL00" FP-ACT1210R-101-2P-TL00_SMD4_3MM2_2MM5-MFG 1455.19,708.66 r270 bottom
L3 "ACT1210R-101-2P-TL00" FP-ACT1210R-101-2P-TL00_SMD4_3MM2_2MM5-MFG 977.88,708.66 r270 bottom
L4 "LQP03TN3N7BZ2J" FP-LQP03TN3N7BZ2J_0603-MFG 2974.87,801 r270 top value=3.7nH
L5 "LQP03TN2N2BZ2B" "FP-LQP03TN2N2BZ2B_0201 (0603)-MFG" 3551,826.8 r0 top value=2.2nH
L6 "LQP03TN3N4BZ2B" "FP-LQP03TN3N4BZ2B_0201 (0603)-MFG" 3054.7,826.77 r0 top value=3.4nH
L7 "LQP03TN3N4BZ2B" "FP-LQP03TN3N4BZ2B_0201 (0603)-MFG" 3119.09,826.77 r0 top value=3.4nH
L8 "LQP03TN3N7BZ2J" FP-LQP03TN3N7BZ2J_0603-MFG 3002.99,841.46 r0 top value=3.7nH
L9 "BLM18HE152SZ1D" 0603 2385.83,811.02 r270 top value="1500 ohm"
L10 "MLZ2012N6R8LTD25" FP-MLZ2012N6R8LTD25_0805-MFG 2527.56,905.51 r180 top value=6.8uH
Logo1 "Texas Instruments" TI_Horizontal_Overlay_Small 90.55,3000 r90 top
Logo2 "WEEE logo" WEEE_Minimum 196.85,1165.35 r0 top
Logo4 "FCC disclaimer" FCC_disclaimer 1039.37,2783.46 r0 top
Logo5 "ESD Susceptible" ESD_Overlay_Medium 168.74,798.46 r0 top
Logo6 "DANGER HIGH VOLTAGE" IEC_HighVoltage_Small 3586.61,3960.63 r90 top
MP1 "DCB-12D" FP-DCB-12D_SPACER-MFG 197.01,197.94 r0 top
MP2 "DCB-12D" FP-DCB-12D_SPACER-MFG 3366.32,197 r0 top
MP3 "DCB-12D" FP-DCB-12D_SPACER-MFG 197.47,4527.77 r0 top
MP4 "DCB-12D" FP-DCB-12D_SPACER-MFG 3740.61,4527.03 r0 top
MP5 "SMS-403C" FP-SMS-403C_RF_SHLD-MFG 4649.61,1870.2 r0 top
MP6 "SMS-403F" FP-SMS-403F_SMT_SHIELD-MFG 2645.95,944.19 r0 top
Q1 "2N7002W-7-F" SOT-323 3818.9,3818.9 r180 bottom value=60V
Q2 "2N7002W-7-F" SOT-323 3818.9,4035.43 r180 bottom value=60V
Q3 "2N7002W-7-F" SOT-323 3818.9,3700.79 r180 bottom value=60V
R1 "CRCW040210K0FKED" 0402 3027.56,2791.34 r180 top value=10.0k
R2 "CRCW040210K0FKED" 0402 3157.48,2791.34 r180 top value=10.0k
R3 "CRCW06030000Z0EA" 0603 1900.15,1660.74 r0 top value=0
R4 "CRCW20105R10JNEF" 2010 2708.66,2078.74 r180 bottom value=5.1
R5 "CRCW04020000Z0ED" 0402 3455.44,2255.91 r90 bottom value=0
R6 "CRCW04020000Z0ED" 0402 3399.87,2247.28 r90 bottom value=0
R7 "CRCW0402110KFKED" 0402 2566.93,1732.28 r270 top value=110k
R8 "CRCW04024M02FKED" 0402 2096.84,1685.04 r270 top value=4.02Meg
R9 "CRCW040210K0FKED" 0402 2933.07,2658.26 r180 top value=10.0k
R10 "CRCW04021M00FKED" 0402 2622.05,1878.34 r180 top value=1.00Meg
R11 "CRCW040210K0FKED" 0402 3094.49,2657.48 r180 top value=10.0k
R12 "CRCW040230K0FKED" 0402 2913.39,1890.35 r0 top value=30.0k
R13 "CRCW060360R4FKEA" 0603 2177.17,2086.61 r180 bottom value=60.4
R14 "CRCW040210K0FKED" 0402 2846.46,2523.62 r180 top value=10.0k
R15 "CRCW040210K0FKED" 0402 2992.13,2519.68 r180 top value=10.0k
R16 "CRCW040210K0FKED" 0402 3507.87,3040.53 r0 bottom value=10.0k
R17 "CRCW0402100KFKED" 0402 3503.94,2992.13 r180 bottom value=100k
R18 "CRCW0402100KFKED" 0402 3503.94,2881.89 r180 bottom value=100k
R19 "CRCW040210K0FKED" 0402 2767.72,2389.76 r180 top value=10.0k
R20 "CRCW04023K30JNED" 0402 3814.96,4122.05 r0 bottom value=3.3k
R21 "CRCW04023K30JNED" 0402 3814.96,4185.04 r180 bottom value=3.3k
R22 "CRCW040210K0FKED" 0402 2909.45,2390.17 r180 top value=10.0k
R23 "CRCW04023K30JNED" 0402 3818.9,3956.69 r0 bottom value=3.3k
R24 "CRCW0402100KFKED" 0402 3818.9,3905.51 r180 bottom value=100k
R25 "CRCW040210K0FKED" 0402 2665.1,2256.31 r180 top value=10.0k
R26 "CRCW0402100KFKED" 0402 3743,4007.58 r270 bottom value=100k
R27 "CRCW040210K0FKED" 0402 3059.06,2295.28 r270 top value=10.0k
R28 "CRCW120618R0FKEA" FP-CRCW120618R0FKEA_1206-MFG 3275.59,3550 r270 top value=18
R29 "CRCW04021K00FKED" 0402 3216.54,3362.2 r270 top value=1.00k
R30 "CRCW120618R0FKEA" FP-CRCW120618R0FKEA_1206-MFG 3275.59,3550 r270 bottom value=18
R31 "CRCW120618R0FKEA" FP-CRCW120618R0FKEA_1206-MFG 3157.48,3550 r270 top value=18
R32 "CRCW04021K00FKED" 0402 3098.43,3362.2 r270 top value=1.00k
R33 "CRCW120618R0FKEA" FP-CRCW120618R0FKEA_1206-MFG 3157.48,3550 r270 bottom value=18
R34 "CRCW120618R0FKEA" FP-CRCW120618R0FKEA_1206-MFG 3041.76,3550 r270 top value=18
R35 "CRCW04021K00FKED" 0402 2984.25,3362.2 r270 top value=1.00k
R36 "CRCW120618R0FKEA" FP-CRCW120618R0FKEA_1206-MFG 3041.76,3550 r270 bottom value=18
R37 "CRCW120618R0FKEA" FP-CRCW120618R0FKEA_1206-MFG 2925.2,3550 r270 top value=18
R38 "CRCW04021K00FKED" 0402 2866.14,3362.2 r270 top value=1.00k
R39 "CRCW120618R0FKEA" FP-CRCW120618R0FKEA_1206-MFG 2925.2,3550 r270 bottom value=18
R40 "CRCW120618R0FKEA" FP-CRCW120618R0FKEA_1206-MFG 2811.02,3550 r270 top value=18
R41 "CRCW04021K00FKED" 0402 2751.97,3362.2 r270 top value=1.00k
R42 "CRCW120618R0FKEA" FP-CRCW120618R0FKEA_1206-MFG 2811.02,3550 r270 bottom value=18
R43 "CRCW120618R0FKEA" FP-CRCW120618R0FKEA_1206-MFG 2692.91,3550 r270 top value=18
R44 "CRCW08050000Z0EA" 0805_HV 3200.79,4503.94 r180 top value=0
R45 "CRCW08050000Z0EA" 0805_HV 3114.17,4173.23 r180 top value=0
R46 "CRCW04021K00FKED" 0402 2614.17,3362.2 r270 top value=1.00k
R47 "CRCW120618R0FKEA" FP-CRCW120618R0FKEA_1206-MFG 2692.91,3550 r270 bottom value=18
R48 "CRCW08050000Z0EA" 0805_HV 3074.8,4522.99 r270 top value=0
R49 "CRCW08050000Z0EA" 0805_HV 3031.5,4401.57 r180 top value=0
R50 "CRCW120618R0FKEA" FP-CRCW120618R0FKEA_1206-MFG 2283.46,3550 r270 top value=18
R51 "CRCW04021K00FKED" 0402 2228.35,3366.14 r270 top value=1.00k
R52 "CRCW120618R0FKEA" FP-CRCW120618R0FKEA_1206-MFG 2283.46,3550 r270 bottom value=18
R53 "CRCW08050000Z0EA" 0805_HV 2996.06,4523.62 r90 top value=0
R54 "CRCW08050000Z0EA" 0805_HV 2956.69,4173.23 r180 top value=0
R55 "CRCW120618R0FKEA" FP-CRCW120618R0FKEA_1206-MFG 2169.29,3550 r270 top value=18
R56 "CRCW08050000Z0EA" 0805_HV 2921.26,4523.62 r270 top value=0
R57 "CRCW08050000Z0EA" 0805_HV 2874.02,4401.57 r0 top value=0
R58 "CRCW04021K00FKED" 0402 2102.36,3366.14 r270 top value=1.00k
R59 "CRCW120618R0FKEA" FP-CRCW120618R0FKEA_1206-MFG 2169.29,3550 r270 bottom value=18
R60 "CRCW08050000Z0EA" 0805_HV 2838.58,4523.62 r90 top value=0
R61 "CRCW08050000Z0EA" 0805_HV 2795.28,4173.23 r180 top value=0
R62 "CRCW120618R0FKEA" FP-CRCW120618R0FKEA_1206-MFG 2035.43,3550 r270 top value=18
R63 "CRCW04021K00FKED" 0402 1972.44,3366.14 r270 top value=1.00k
R64 "CRCW120618R0FKEA" FP-CRCW120618R0FKEA_1206-MFG 2035.43,3550 r270 bottom value=18
R65 "CRCW120618R0FKEA" FP-CRCW120618R0FKEA_1206-MFG 1909.45,3550 r270 top value=18
R66 "CRCW0402511RFKED" 0402 2433.07,3417.32 r90 top value=511
R67 "CRCW04021K00FKED" 0402 1850.39,3366.14 r270 top value=1.00k
R68 "CRCW120618R0FKEA" FP-CRCW120618R0FKEA_1206-MFG 1909.45,3550 r270 bottom value=18
R69 "CRCW120618R0FKEA" FP-CRCW120618R0FKEA_1206-MFG 1787.4,3550 r270 top value=18
R70 "CRCW04021K00FKED" 0402 1724.41,3366.14 r270 top value=1.00k
R71 "CRCW120618R0FKEA" FP-CRCW120618R0FKEA_1206-MFG 1787.4,3550 r270 bottom value=18
R72 "CRCW08050000Z0EA" 0805_HV 2712.6,4503.94 r180 top value=0
R73 "CRCW08050000Z0EA" 0805_HV 2488.19,4311.02 r180 top value=0
R74 "CRCW120618R0FKEA" FP-CRCW120618R0FKEA_1206-MFG 1661.42,3550 r270 top value=18
R75 "CRCW08050000Z0EA" 0805_HV 2409.45,4417.32 r180 top value=0
R76 "CRCW08050000Z0EA" 0805_HV 2125.98,4401.57 r180 top value=0
R77 "CRCW04021K00FKED" 0402 1582.68,3366.14 r270 top value=1.00k
R78 "CRCW120618R0FKEA" FP-CRCW120618R0FKEA_1206-MFG 1661.42,3550 r270 bottom value=18
R79 "CRCW08050000Z0EA" 0805_HV 2251.97,4448.82 r90 top value=0
R80 "CRCW08050000Z0EA" 0805_HV 2047.24,4173.23 r180 top value=0
R81 "CRCW120618R0FKEA" FP-CRCW120618R0FKEA_1206-MFG 1350.39,3550 r270 bottom value=18
R82 "CRCW04021K00FKED" 0402 1295.28,3366.14 r270 top value=1.00k
R83 "CRCW120618R0FKEA" FP-CRCW120618R0FKEA_1206-MFG 1350.39,3550 r270 top value=18
R84 "CRCW08050000Z0EA" 0805_HV 2125.98,4488.19 r180 top value=0
R85 "CRCW08050000Z0EA" 0805_HV 1968.5,4401.57 r180 top value=0
R86 "CRCW120618R0FKEA" FP-CRCW120618R0FKEA_1206-MFG 1232.28,3550 r270 top value=18
R87 "CRCW08050000Z0EA" 0805_HV 1889.76,4173.23 r180 top value=0
R88 "CRCW04021K00FKED" 0402 1169.29,3366.14 r270 top value=1.00k
R89 "CRCW120618R0FKEA" FP-CRCW120618R0FKEA_1206-MFG 1232.28,3550 r270 bottom value=18
R90 "CRCW08050000Z0EA" 0805_HV 1811.02,4401.57 r180 top value=0
R91 "CRCW120618R0FKEA" FP-CRCW120618R0FKEA_1206-MFG 1106.3,3550 r270 bottom value=18
R92 "CRCW04021K00FKED" 0402 1047.24,3366.14 r270 top value=1.00k
R93 "CRCW120618R0FKEA" FP-CRCW120618R0FKEA_1206-MFG 1106.3,3550 r270 top value=18
R94 "CRCW120618R0FKEA" FP-CRCW120618R0FKEA_1206-MFG 988.19,3550 r270 top value=18
R95 "CRCW04021K00FKED" 0402 925.2,3366.14 r270 top value=1.00k
R96 "CRCW120618R0FKEA" FP-CRCW120618R0FKEA_1206-MFG 988.19,3550 r270 bottom value=18
R97 "CRCW120618R0FKEA" FP-CRCW120618R0FKEA_1206-MFG 866.14,3550 r270 top value=18
R98 "CRCW04021K00FKED" 0402 807.09,3366.14 r270 top value=1.00k
R99 "CRCW120618R0FKEA" FP-CRCW120618R0FKEA_1206-MFG 866.14,3550 r270 bottom value=18
R100 "CRCW08050000Z0EA" 0805_HV 1452.76,4330.71 r180 top value=0
R101 "CRCW120618R0FKEA" FP-CRCW120618R0FKEA_1206-MFG 748.03,3550 r270 top value=18
R102 "CRCW08050000Z0EA" 0805_HV 1141.73,4173.23 r180 top value=0
R103 "CRCW04021K00FKED" 0402 688.98,3366.14 r270 top value=1.00k
R104 "CRCW120618R0FKEA" FP-CRCW120618R0FKEA_1206-MFG 748.03,3550 r270 bottom value=18
R105 "CRCW08050000Z0EA" 0805_HV 1062.99,4397.64 r180 top value=0
R106 "CRCW120618R0FKEA" FP-CRCW120618R0FKEA_1206-MFG 625.98,3550 r270 top value=18
R107 "CRCW04021K00FKED" 0402 562.99,3366.14 r270 top value=1.00k
R108 "CRCW120618R0FKEA" FP-CRCW120618R0FKEA_1206-MFG 625.98,3550 r270 bottom value=18
R109 "CRCW08050000Z0EA" 0805_HV 984.25,4173.23 r180 top value=0
R110 "CRCW08050000Z0EA" 0805_HV 905.51,4397.64 r180 top value=0
R111 "CRCW08050000Z0EA" 0805_HV 826.77,4173.23 r180 top value=0
R112 "CRCW08050000Z0EA" 0805_HV 2574.8,4559.06 r270 top value=0
R113 "CRCW08050000Z0EA" 0805_HV 2370.08,4538.73 r270 top value=0
R114 "CRCW08050000Z0EA" 0805_HV 2133.21,4582.68 r0 top value=0
R115 "CRCW08050000Z0EA" 0805_HV 2011.81,4523.62 r270 top value=0
R116 "CRCW08050000Z0EA" 0805_HV 1893.7,4523.62 r270 top value=0
R117 "CRCW08050000Z0EA" 0805_HV 1791.34,4523.62 r270 top value=0
R118 "CRCW08050000Z0EA" 0805_HV 1495.77,4495.11 r270 top value=0
R119 "CRCW06030000Z0EA" 0603 1497.64,2342.52 r270 top value=0
R120 "CRCW040251R1FKED" 0402 1484.25,1511.81 r270 top value=51.1
R121 "CRCW06030000Z0EA" 0603 1484.25,1377.95 r270 top value=0
R122 "RC0603JR-070RL" 0603 1492.13,649.61 r270 top value=0
R123 "CRCW0603499RFKEA" 0603 1452.76,1665.35 r0 top value=499
R124 "CRCW06031K00FKEA" 0603 1387.47,1543.34 r0 top value=1.00k
R125 "CRCW0603499RFKEA" 0603 1326.77,1665.35 r0 top value=499
R126 "CRCW06030000Z0EA" 0603 1345.72,2342.52 r270 top value=0
R127 "CRCW040251R1FKED" 0402 1295.28,1511.81 r270 top value=51.1
R128 "CRCW06030000Z0EA" 0603 1295.28,1377.95 r270 top value=0
R129 "RC0603JR-070RL" 0603 1421.26,649.61 r270 top value=0
R130 "CRCW06030000Z0EA" 0603 1140.07,2342.52 r270 top value=0
R131 "CRCW040251R1FKED" 0402 960.63,1519.68 r270 top value=51.1
R132 "CRCW06030000Z0EA" 0603 960.63,1377.95 r270 top value=0
R133 "RC0603JR-070RL" 0603 940.94,653.54 r270 top value=0
R134 "CRCW0603499RFKEA" 0603 992.13,1665.35 r180 top value=499
R135 "CRCW06031K00FKEA" 0603 1058.12,1543.31 r180 top value=1.00k
R136 "CRCW0603499RFKEA" 0603 1118.11,1665.35 r180 top value=499
R137 "CRCW06030000Z0EA" 0603 1289.68,2342.52 r270 top value=0
R138 "CRCW040251R1FKED" 0402 1149.61,1511.81 r270 top value=51.1
R139 "CRCW06030000Z0EA" 0603 1149.61,1377.95 r270 top value=0
R140 "RC0603JR-070RL" 0603 1011.81,653.54 r270 top value=0
R141 "CRCW04020000Z0ED" 0402 1822.83,511.81 r180 top value=0
R142 "CRCW0402100KFKED" 0402 1933.07,511.81 r180 top value=100k
R143 "CRCW0402100KFKED" 0402 2023.62,511.81 r0 top value=100k
R144 "CRCW04020000Z0ED" 0402 1818.9,1035.43 r270 top value=0
R145 "CRCW040210K0FKED" 0402 1852.23,775.47 r270 top value=10.0k
R146 "CRCW04020000Z0ED" 0402 1754.15,1105.98 r270 top value=0
R147 "CRCW040210K0FKED" 0402 1988.19,951.56 r90 top value=10.0k
R148 "CRCW040210K0FKED" 0402 1929.13,1039.37 r270 top value=10.0k
R149 "CRCW04020000Z0ED" 0402 3280.19,1309.42 r180 top value=0
R150 "CRCW04020000Z0ED" 0402 3376.53,1490.43 r270 top value=0
R151 "CRCW04022K20JNED" 0402 3031.5,1326.77 r180 bottom value=2.2k
R152 "CRCW04022K20JNED" 0402 2923,1350.26 r180 bottom value=2.2k
R153 "CRCW0402100KFKED" 0402 2606.3,1314.96 r270 top value=100k
R154 "CRCW0402100KJNED" 0402 2657.48,1314.96 r270 top value=100k
R155 "CRCW0402100KFKED" 0402 2708.66,1314.96 r270 top value=100k
R156 "CRCW0402100KFKED" 0402 2527.56,1251.97 r180 top value=100k
R157 "CRCW0402100KFKED" 0402 2586.61,1169.29 r270 top value=100k
R158 "CRCW0402100KJNED" 0402 2574.8,582.68 r270 top value=100k
R159 "CRCW2010100RFKEFHP" FP-CRCW2010100RFKEFHP_2010-MFG 3389.76,3913.39 r90 bottom value=100
R160 "CRCW2010100RFKEFHP" FP-CRCW2010100RFKEFHP_2010-MFG 3228.35,3913.39 r270 bottom value=100
R161 "CRCW2010100RFKEFHP" FP-CRCW2010100RFKEFHP_2010-MFG 3055.12,3913.39 r90 bottom value=100
R162 "CRCW2010100RFKEFHP" FP-CRCW2010100RFKEFHP_2010-MFG 2897.64,3913.39 r270 bottom value=100
R163 "CRCW2010100RFKEFHP" FP-CRCW2010100RFKEFHP_2010-MFG 2744.09,3913.39 r90 bottom value=100
R164 "CRCW2010100RFKEFHP" FP-CRCW2010100RFKEFHP_2010-MFG 2586.6,3913.39 r270 bottom value=100
R165 "CRCW2010100RFKEFHP" FP-CRCW2010100RFKEFHP_2010-MFG 2425.2,3913.39 r90 bottom value=100
R166 "CRCW2010100RFKEFHP" FP-CRCW2010100RFKEFHP_2010-MFG 2259.84,3913.39 r270 bottom value=100
R167 "CRCW2010100RFKEFHP" FP-CRCW2010100RFKEFHP_2010-MFG 2102.36,3913.39 r90 bottom value=100
R168 "CRCW2010100RFKEFHP" FP-CRCW2010100RFKEFHP_2010-MFG 1925.2,3913.39 r270 bottom value=100
R169 "CRCW2010100RFKEFHP" FP-CRCW2010100RFKEFHP_2010-MFG 1759.84,3913.39 r90 bottom value=100
R170 "CRCW2010100RFKEFHP" FP-CRCW2010100RFKEFHP_2010-MFG 1598.43,3913.39 r270 bottom value=100
R171 "CRCW2010100RFKEFHP" FP-CRCW2010100RFKEFHP_2010-MFG 1405.51,3913.39 r90 bottom value=100
R172 "CRCW2010100RFKEFHP" FP-CRCW2010100RFKEFHP_2010-MFG 1240.16,3913.39 r270 bottom value=100
R173 "CRCW2010100RFKEFHP" FP-CRCW2010100RFKEFHP_2010-MFG 1082.68,3913.39 r90 bottom value=100
R174 "CRCW2010100RFKEFHP" FP-CRCW2010100RFKEFHP_2010-MFG 917.32,3913.39 r270 bottom value=100
R175 "CRCW2010100RFKEFHP" FP-CRCW2010100RFKEFHP_2010-MFG 748.03,3913.39 r90 bottom value=100
R176 "CRCW2010100RFKEFHP" FP-CRCW2010100RFKEFHP_2010-MFG 582.68,3913.39 r270 bottom value=100
RT1 "NTCGS163JF103FT7" FP-NTCGS163JF103FT7_0603-MFG 3007.87,2724.99 r0 top value=10k
RT2 "NTCGS163JF103FT7" FP-NTCGS163JF103FT7_0603-MFG 2925.2,2591.54 r0 top value=10k
RT3 "NTCGS163JF103FT7" FP-NTCGS163JF103FT7_0603-MFG 2846.46,2456.9 r0 top value=10k
RT4 "NTCGS163JF103FT7" FP-NTCGS163JF103FT7_0603-MFG 2751.97,2323.04 r0 top value=10k
RT5 "NTCGS163JF103FT7" FP-NTCGS163JF103FT7_0603-MFG 2913.79,2271.65 r180 top value=10k
S1 "TDA06H0SB1" SW_TDA06H0SB1 3543.31,2952.76 r0 top
S2 "TDA06H0SB1" SW_TDA06H0SB1 3543.31,2165.35 r0 top
S3 "219-2MST" SW_219-2MST 1818.9,1472.44 r0 top
S4 "TDA06H0SB1" SW_TDA06H0SB1 2988.19,3897.64 r90 top
S5 "TDA06H0SB1" SW_TDA06H0SB1 2000,3897.64 r90 top
S6 "TDA06H0SB1" SW_TDA06H0SB1 988.19,3893.7 r90 top
SH-J1 "SNT-100-BK-G" SNT-100-BK-G 4590.55,653.54 r90 top value=1x2
SH-J2 "SNT-100-BK-G" SNT-100-BK-G 4153.54,661.42 r90 top value=1x2
SH-J3 "SNT-100-BK-G" SNT-100-BK-G 4933.07,1011.81 r90 top value=1x2
SH-J4 "SNT-100-BK-G" SNT-100-BK-G 4610.24,1011.81 r90 top value=1x2
SH-J5 "SNT-100-BK-G" SNT-100-BK-G 4275.59,1005.12 r90 top value=1x2
T1 "HMU1228NL" FP-HMU1228NL_SMT_TRANSFORMER_8MM89_10MM09-MFG 1456.69,1003.94 r270 top
T2 "HMU1228NL" FP-HMU1228NL_SMT_TRANSFORMER_8MM89_10MM09-MFG 976.38,1003.94 r270 top
TP1 "GND" Keystone1598-2 530.93,4569.11 r0 top
TP2 "BAT" Keystone5012 578.74,1893.7 r90 top
TP3 "LDOIN" Keystone5012 1763.98,1749.65 r90 top
TP4 "TSREF" Keystone5012 1968.5,1929.13 r90 top
TP5 "AVDD" Keystone5012 582.68,2157.48 r270 top
TP6 "DVDD" Keystone5012 574.8,2405.51 r90 top
TP7 "REF_CAP" Keystone5012 1811.02,2047.24 r270 top
TP8 "VPWR" Keystone1598-2 3460.63,4570.87 r0 top
TP9 "GND" Keystone1598-2 401.57,858.27 r0 top
TP10 "TP_SM_1MM" TP_SM_1MM#1 2925.2,1133.86 r90 top
TP11 "TP_SM_1MM" TP_SM_1MM#2 2440.53,948.48 r90 top
U1 "CC2662R1FTWRGZRQ1" RGZ0048R-MFG 2779.53,925.2 r180 top
U2 "BQ79718VPAPRQ1" PAP0064F-MFG 1811.02,2519.68 r180 top locked
U3 "TPD4E05U06QDQARQ1" DQA0010A 3673.59,2593.74 r0 top
U4 "TPD4E05U06QDQARQ1" DQA0010A 3765.96,2225.2 r0 top
U5 "TPD4E05U06QDQARQ1" DQA0010A 3765.96,3022 r0 top
U6 "DESD1CAN2SOQ-7" FP-DESD1CAN2SOQ-7_SOT23-MFG 1389.76,1444.88 r270 top
U7 "DESD1CAN2SOQ-7" FP-DESD1CAN2SOQ-7_SOT23-MFG 1055.12,1444.88 r270 top
U8 "TPD4E05U06QDQARQ1" DQA0010A 2007.87,365.39 r90 top
U9 "TPS3436BDADADDFRQ1" DDF0008A-MFG 1897.64,897.64 r90 top
U10 "TPS71533QDCKRQ1" DCK0005A_N 1807.09,1204.72 r180 top
U11 "TPD4E05U06QDQARQ1" DQA0010A 2745.65,531.5 r90 top
U12 "TPD4E05U06QDQARQ1" DQA0010A 2990,511.81 r180 top
U13 "TXU0204QPWRQ1" PW0014A-MFG 3500,1437.01 r90 top
U14 "TPD4E05U06QDQARQ1" DQA0010A 2314.5,550.62 r90 top
U15 "LM5168PQDDARQ1" DDA0008E-MFG 2833.66,1752.17 r180 top
Y1 "DST1610A 7BG03276AAC" "FP-DST1610A 7BG03276AAC_SMD2-MFG" 3010.12,950.87 r300 top
Y2 "CX2016DB48000C0FRLC1" FP-CX2016DB48000C0FRLC1_SMT4_2MM05_1MM65-MFG 2858.27,610.24 r322 top
ZZ1 "These assemblies are ESD sensitive, ESD precautions shall be observed." AssemblyNote -35.43,5228.35 r0 top
ZZ2 "These assemblies must be clean and free from flux and all contaminants. Use of no clean flux is not acceptable." AssemblyNote -35.75,5149.61 r0 top
ZZ3 "These assemblies must comply with workmanship standards IPC-A-610 Class 2, unless otherwise specified." AssemblyNote -39.37,5066.93 r0 top
ZZ4 "Via in PADs must be filled" AssemblyNote -39.37,4988.19 r0 top

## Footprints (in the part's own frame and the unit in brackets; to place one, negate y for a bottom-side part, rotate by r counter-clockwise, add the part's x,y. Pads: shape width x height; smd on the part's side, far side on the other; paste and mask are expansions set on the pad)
0402 [mm] "0402 from SM-752 data"
  rect 0.8x0.6 smd: 1(-0.6,0) 2(0.6,0)
  silkscreen extent -1.22,-0.52 1.22,0.52, body extent -0.55,-0.3 0.55,0.3, height 0.6
0402_070 [mil] "SMD, 2-Leads, Body 1.2x0.7mm, Height 0.7mm"
  rect 15x24 smd: 1(-20,0) 2(20,0)
  body extent -24,-14 24,14, height 28
0603 [mm] "0603 from SM-752 data"
  rect 1x0.95 smd: 1(-0.8,0) 2(0.8,0)
  silkscreen extent -1.52,-0.69 1.52,0.69, body extent -0.87,-0.47 0.87,0.47, height 1
0805_HV [mil] "0805 with 30mil clearance between pads"
  rect 50x63 smd: 1(-40,0) 2(40,0)
  silkscreen extent -74,-40 74,40, body extent -43,-29 43,29, height 57
2010 [mm] "Chip Capacitor, Body 5.08x2.54mm, IPC Medium Density"
  rect 1.6x2.7 smd: 1(-2.3,0) 2(2.3,0)
  silkscreen extent -3.42,-1.65 3.42,1.65, body extent -2.73,-1.45 2.73,1.45, height 1.66
ANTENNA_DN007A [mm] "SMD, 3-Leads"
  rect 0.4x0.2 smd paste-2 mask-2: 1(0,0)
  rect 0.9x0.2 smd paste-2 mask-2: 2(1.18,0.01) 3(3.37,0)
  Top Layer region: 10.84,-0.63 10.84,-6.775 -14.715,-6.775 -14.715,-5.59 1.685,-5.59 1.685,-3.765 0.685,-3.765 0.685,-3.271 -0.225,-1.951 -0.225,0.11 0.21,0.11 0.21,-1.816 0.737,-2.58 3.86,-2.58 3.86,-3.765 2.86,-3.765 2.86,-4.59 8.685,-4.59 8.685,-1.895 0.685,-1.895 0.685,0.11 1.66,0.11 1.66,-0.63 2.885,-0.63 2.885,0.11 3.86,0.11 3.86,-0.63
AssemblyNote [mil] "Assembly Note"
CONN_PEC02SAAN [mm] "SULLINS"
  rrect7% 1.5x1.5 hole 1.016: 1(-1.27,0)
  round 1.5 hole 1.016: 2(1.27,0)
  silkscreen extent -2.54,-1.52 2.54,1.27, body extent -2.54,-1.27 2.54,1.27, height 8.38
DCK0005A_N [mm] "SOT353, 5-Leads, Body 2x1.3mm, Pitch 0.65mm, Lead Span 2.1mm, IPC Medium Density"
  rrect25% 0.85x0.4 smd: 1(-1.125,0.65) 2(-1.125,0) 3(-1.125,-0.65) 4(1.125,-0.65) 5(1.125,0.65)
  silkscreen extent -1.48,-1.02 0.55,1.1, body extent -1.14,-1 1.14,1, height 0.95
DDA0008E-MFG [mm]
  rrect20% 2.2x0.5 smd paste-1000 mask+0: 1(-2.875,1.905) 2(-2.875,0.635) 3(-2.875,-0.635) 4(-2.875,-1.905) 5(2.875,-1.905) 6(2.875,-0.635) 7(2.875,0.635) 8(2.875,1.905)
  rrect3% 2.95x4.9 smd paste-1000 mask-1000: 9(0,0)
  silkscreen extent -3.55,-2.83 2,2.93, body extent -3,-2.45 3,2.45, height 1.7
DDF0008A-MFG [mm]
  rrect22% 1.05x0.45 smd paste+0 mask+0: 1(-1.3,0.975) 2(-1.3,0.325) 3(-1.3,-0.325) 4(-1.3,-0.975) 5(1.3,-0.975) 6(1.3,-0.325) 7(1.3,0.325) 8(1.3,0.975)
  silkscreen extent -1.66,1.86 -1.41,2.11, body extent -1.92,-1.73 1.92,1.73, height 0.25
DQA0010A [mm] "SON, 10-Leads, Body 1x2.5mm, Pitch 0.5mm, TI Recommended"
  rrect50% 0.565x0.2 smd: 1(-0.417,1) 2(-0.417,0.5) 4(-0.417,-0.5) 5(-0.417,-1) 6(0.417,-1) 7(0.417,-0.5) 9(0.417,0.5) 10(0.417,1)
  rrect28% 0.565x0.36 on Top Paste: 3(-0.417,0) 8(0.417,0)
  rrect25% 0.565x0.4 smd paste-0.2: 3(-0.417,0) 8(0.417,0)
  body extent -0.55,-1.3 0.55,1.3, height 0.56
ESD_Overlay_Medium [mil]
  silkscreen extent -127,-109 125,110
FCC_disclaimer [mil]
Fiducial10-30 [mm]
  round 1 smd mask+1: 1(0,0)
  Top Layer keep-out circle w1.678: c0,0 r0.75
FP-1206Y2K00222KET_1206-MFG [mm]
  rrect9% 1.15x1.8 smd paste+0 mask+0: 1(-1.5,0) 2(1.5,0)
  body extent -1.6,-0.8 1.6,0.8, height 1.7
FP-ACT1210R-101-2P-TL00_SMD4_3MM2_2MM5-MFG [mm]
  rrect17% 1.05x0.6 smd paste+0 mask+0: 1(-1.525,0.5) 2(-1.525,-0.5) 3(1.525,-0.5) 4(1.525,0.5)
  silkscreen extent -2.72,-1.35 1.95,1.35, body extent -1.95,-1.25 1.95,1.25, height 2.5
FP-CRCW120618R0FKEA_1206-MFG [mm]
  rrect10% 1.05x1.8 smd paste+0 mask+0: 1(-1.275,0) 2(1.275,0)
  silkscreen extent -0.38,-0.87 0.38,0.87, body extent -1.9,-1 1.9,1, height 0.25
FP-CRCW2010100RFKEFHP_2010-MFG [mm]
  rrect8% 1.2x2.7 smd paste+0 mask+0: 1(-2.45,0) 2(2.45,0)
  silkscreen extent -1.47,-1.33 1.47,1.33, body extent -2.5,-1.25 2.5,1.25, height 0.7
FP-CX2016DB48000C0FRLC1_SMT4_2MM05_1MM65-MFG [mil]
  round 19.93 smd paste+0 mask+0: 1(-32.23,-24.36) 2(32.23,-24.36) 3(32.23,24.36) 4(-32.23,24.36)
  Top Layer region: -25.2,-10.63 -24.14,-14.57 -21.26,-17.45 -17.32,-18.5 -17.32,-18.5 -13.78,-18.5 -13.78,-35.43 -43.31,-35.43 -43.31,-5.91 -25.2,-5.91
  Top Layer region: 25.2,10.63 24.6,13.64 22.89,16.2 20.34,17.9 17.32,18.5 17.32,18.5 13.78,18.5 13.78,35.43 43.31,35.43 43.31,5.91 25.2,5.91
  Top Layer region: 25.2,-10.63 24.14,-14.57 21.26,-17.45 17.32,-18.5 17.32,-18.5 13.78,-18.5 13.78,-35.43 43.31,-35.43 43.31,-5.91 25.2,-5.91
  Top Layer region: -25.2,10.63 -24.6,13.64 -22.89,16.2 -20.34,17.9 -17.32,18.5 -17.32,18.5 -13.78,18.5 -13.78,35.43 -43.31,35.43 -43.31,5.91 -25.2,5.91
  silkscreen extent -35,-62 -26,-52, body extent -47,-39 47,39, height 10
FP-DCB-12D_SPACER-MFG [mm]
  round 3 hole 3 unplated paste-2539.97 mask+0: ""(0,0)
  body extent -3.75,-3.25 3.75,3.25, height 0.25
FP-DESD1CAN2SOQ-7_SOT23-MFG [mm] "Recommended Land Pattern"
  rrect13% 0.9x0.8 smd paste+0 mask+0: 1(-1,0.95) 2(-1,-0.95) 3(1,0)
  silkscreen extent -0.18,-1.5 0.7,1.5, body extent -1.2,-1.45 1.2,1.45, height 1.1
"FP-DST1610A 7BG03276AAC_SMD2-MFG" [mm]
  rrect14% 0.7x1.2 smd paste+0 mask+0: 1(-0.55,0) 2(0.55,0)
  body extent -1,-0.7 1,0.7, height 0.25
FP-GCJ32DC72A475KE01L_1210-MFG [mm]
  rrect9% 1.1x2.05 smd paste+0 mask+0: 1(-1.65,0) 2(1.65,0)
  silkscreen extent -1.8,-1.4 1.8,1.4, body extent -1.6,-1.25 1.6,1.25, height 2.3
FP-GCM32EC71A476KE02K_1210-MFG [mm]
  rrect9% 1.1x2.05 smd paste+0 mask+0: 1(-1.65,0) 2(1.65,0)
  silkscreen extent -0.72,-1.35 0.72,1.35, body extent -2.3,-1.45 2.3,1.45, height 0.25
FP-GCM155R71E473KA55D_0402-MFG [mm]
  rrect25% 0.4x0.5 smd paste+0 mask+0: 1(-0.4,0) 2(0.4,0)
  body extent -0.5,-0.25 0.5,0.25, height 0.55
FP-GCM1555C1H560FA16D_0402-MFG [mm]
  rrect25% 0.4x0.5 smd paste+0 mask+0: 1(-0.4,0) 2(0.4,0)
  silkscreen extent -0.53,-0.65 0.53,0.65, body extent -0.7,-0.38 0.7,0.38, height 0.25
FP-GCQ0335C1H1R0WB01D_0201-MFG [mm]
  rrect40% 0.25x0.3 smd paste+0 mask+0: 1(-0.238,0) 2(0.238,0)
  body extent -0.46,-0.27 0.46,0.27, height 0.25
FP-GCQ0335C1H1R1BB01D_0201-MFG [mm] "Recommended Land Pattern"
  rrect40% 0.25x0.3 smd paste+0 mask+0: 1(-0.238,0) 2(0.238,0)
  body extent -0.46,-0.27 0.46,0.27, height 0.25
FP-GCQ0335C1H120GB01D_0201-MFG [mm]
  rrect40% 0.25x0.3 smd paste+0 mask+0: 1(-0.238,0) 2(0.238,0)
  body extent -0.46,-0.27 0.46,0.27, height 0.25
FP-HMU1228NL_SMT_TRANSFORMER_8MM89_10MM09-MFG [mm]
  rrect13% 1.585x0.76 smd paste+0 mask+0: 1(-5.937,2.54) 2(-5.937,0) 3(-5.937,-2.54) 4(5.937,-2.54) 5(5.937,0) 6(5.937,2.54)
  silkscreen extent -7.5,-4.51 5.08,4.51, body extent -6.83,-4.61 6.83,4.61, height 0.25
"FP-LQP03TN2N2BZ2B_0201 (0603)-MFG" [mm] "Recommended Land Pattern"
  rrect40% 0.3x0.25 smd paste+0 mask+0: 1(-0.275,0) 2(0.275,0)
  body extent -0.53,-0.27 0.53,0.27, height 0.25
"FP-LQP03TN3N4BZ2B_0201 (0603)-MFG" [mm]
  rrect40% 0.3x0.25 smd paste+0 mask+0: 1(-0.275,0) 2(0.275,0)
  body extent -0.53,-0.27 0.53,0.27, height 0.25
FP-LQP03TN3N7BZ2J_0603-MFG [mm]
  rrect40% 0.3x0.25 smd paste+0 mask+0: 1(-0.275,0) 2(0.275,0)
  body extent -0.53,-0.27 0.53,0.27, height 0.25
FP-MLZ2012N6R8LTD25_0805-MFG [mm]
  rrect13% 0.8x1.2 smd paste+0 mask+0: 1(-0.9,0) 2(0.9,0)
  body extent -1.4,-0.82 1.4,0.82, height 0.25
FP-NTCGS163JF103FT7_0603-MFG [mm] "Recommended Land Pattern"
  rrect14% 0.7x0.7 smd paste+0 mask+0: 1(-0.7,0) 2(0.7,0)
  silkscreen extent -0.85,-0.72 0.85,0.72, body extent -1.15,-0.55 1.15,0.55, height 0.25
FP-S14B-PUDSS-1(LF)(SN)_CONN_HDR14-MFG [mm]
  rrect8% 1.2x1.2 hole 0.7 paste-2539.97 mask+0: 1(6,-5.75)
  round 1.2 hole 0.7 paste-2539.97 mask+0: 2(6,-3.75) 3(4,-5.75) 4(4,-3.75) 5(2,-5.75) 6(2,-3.75) 7(0,-5.75) 8(0,-3.75) 9(-2,-5.75) 10(-2,-3.75) 11(-4,-5.75) 12(-4,-3.75) 13(-6,-5.75) 14(-6,-3.75)
  round 1.6 hole 1.6 unplated paste-2539.97 mask+0: ""(-6.9,3.95) ""(6.9,3.95)
  silkscreen extent -8,-7.02 8,6.35, body extent -8,-6.35 8,6.35, height 8.5
FP-SMAJ85A-AT/TR13_SMA-MFG [mm]
  rrect6% 1.75x1.68 smd paste+0 mask+0: 1(-1.815,0) 2(1.815,0)
  silkscreen extent -3.37,-1.4 2.25,1.4, body extent -2.55,-1.33 2.55,1.33, height 2.5
FP-SMS-403C_RF_SHLD-MFG [mil]
  body extent -535,-535 535,535, height 10
FP-SMS-403F_SMT_SHIELD-MFG [mil]
  round 40.65 smd paste+0 mask+0: 1(-508.97,508.97) 5(508.97,508.97) 12(-508.97,-508.97) 16(508.97,-508.97)
  rrect10% 147x39 smd paste+0 mask+0: 2(-236.5,512.5) 3(-0.5,512.5) 4(235.5,512.5) 13(-236.5,-512.5) 14(-0.5,-512.5) 15(235.5,-512.5)
  rrect10% 39x147 smd paste+0 mask+0: 6(-512.5,235.5) 7(512.5,235.5) 8(-512.5,-0.5) 9(512.5,-0.5) 10(-512.5,-236.5) 11(512.5,-236.5)
  Top Layer region: 532,-532 532,-398 493,-398 493,-493 398,-493 398,-532 532,-532
  Top Layer region: -532,-532 -532,-398 -493,-398 -493,-493 -398,-493 -398,-532 -532,-532
  Top Layer region: 532,532 532,398 493,398 493,493 398,493 398,532 532,532
  Top Layer region: -532,532 -398,532 -398,493 -493,493 -493,398 -532,398 -532,532
  body extent -536,-536 536,536, height 10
